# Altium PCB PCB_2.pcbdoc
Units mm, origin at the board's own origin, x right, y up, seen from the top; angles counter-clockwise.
Board outline 42.7 x 42.6 mm, 6 copper layers (Top Layer, Inner1, Inner2, Inner3, Inner4, Bottom Layer); 29 components, 49 nets, 154 pads, 103 vias.
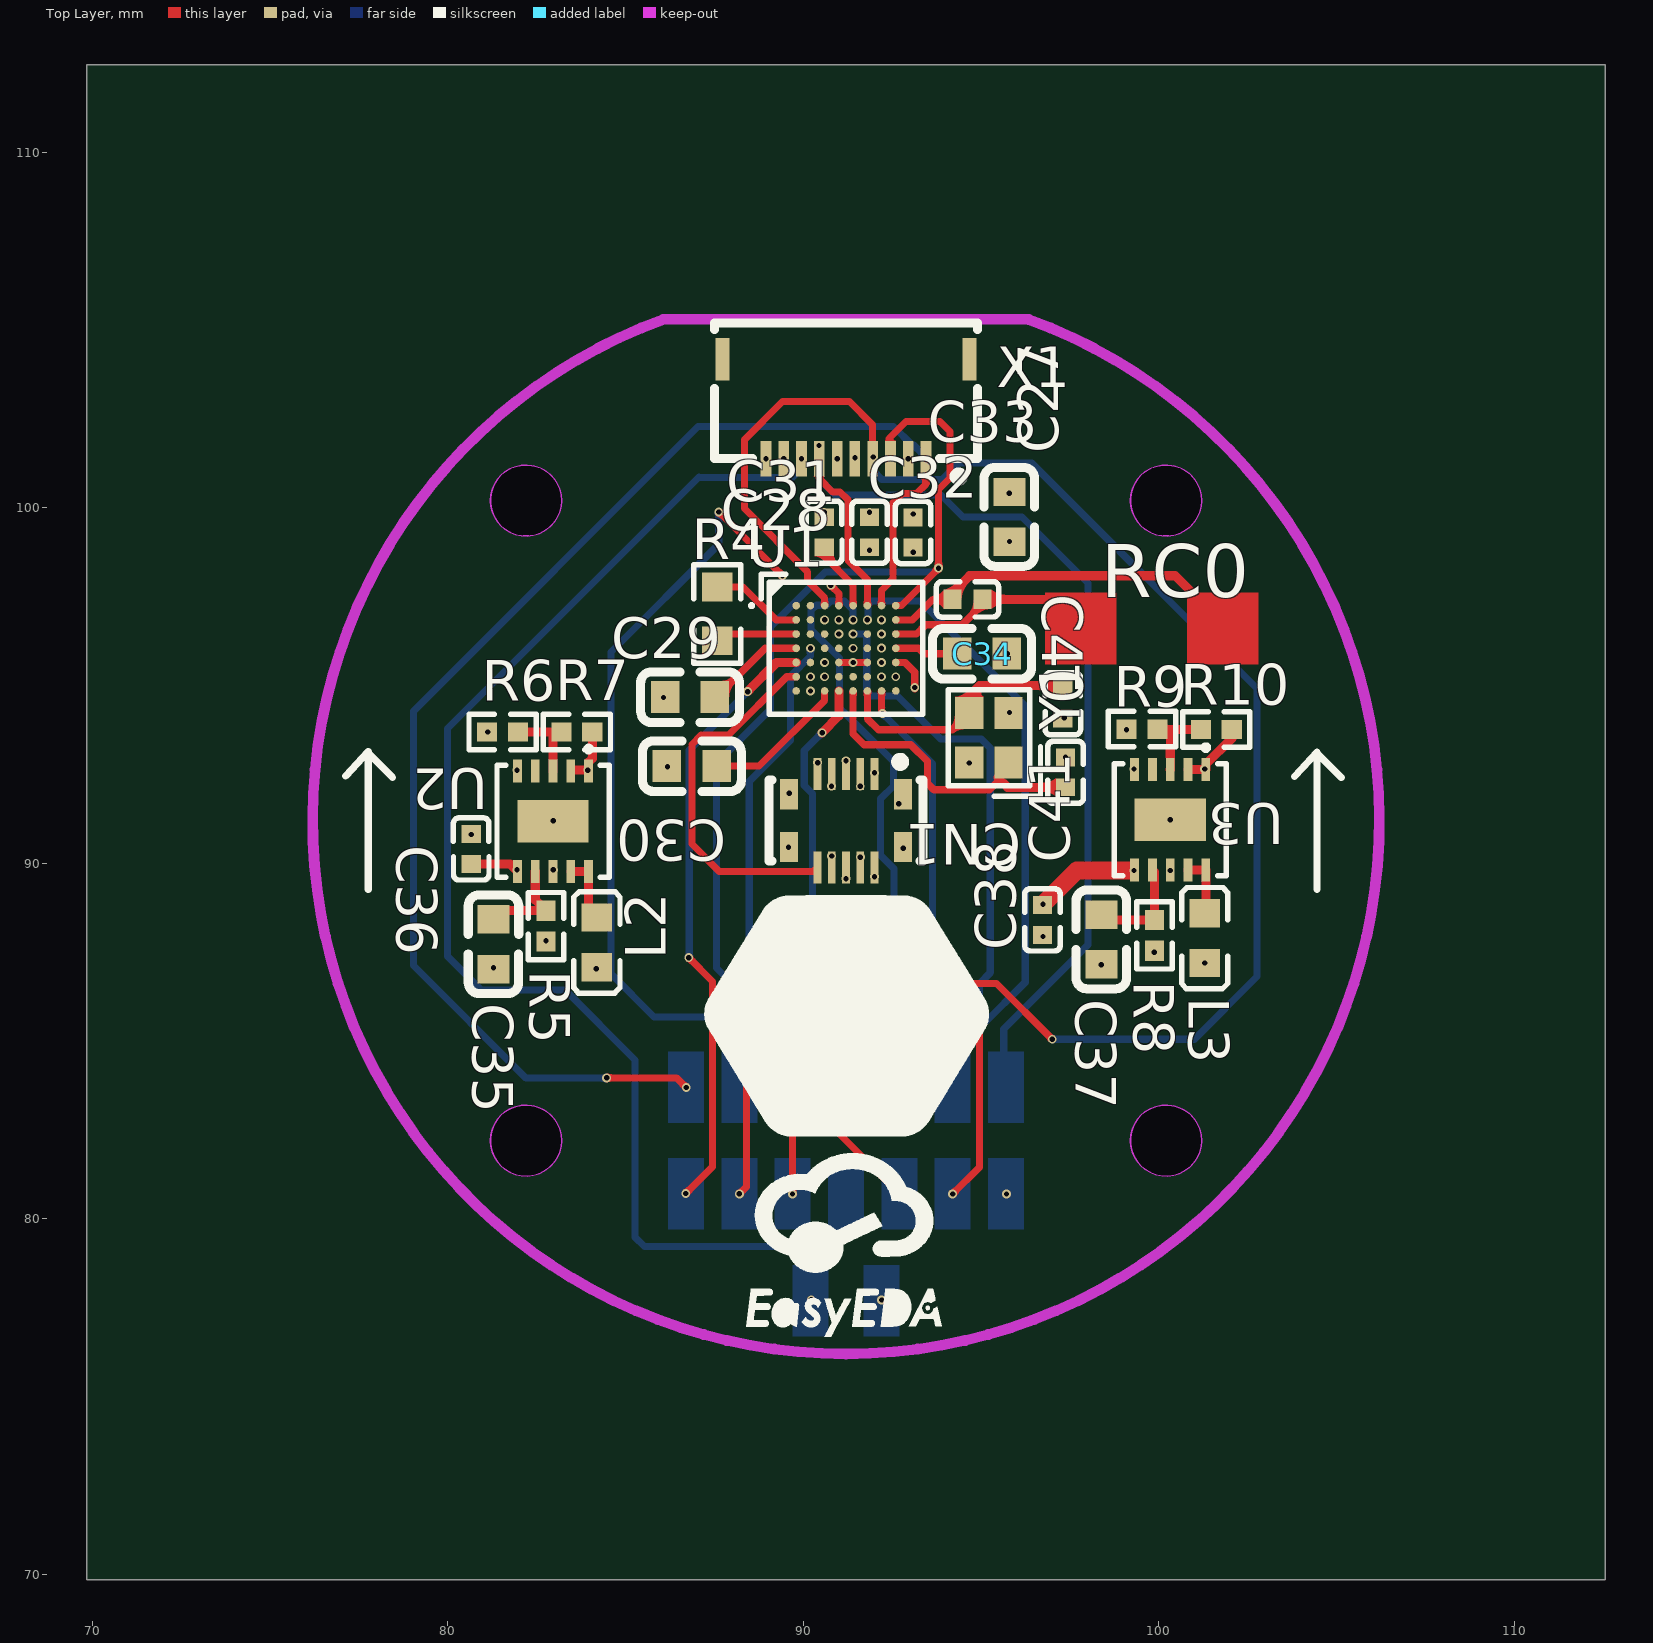
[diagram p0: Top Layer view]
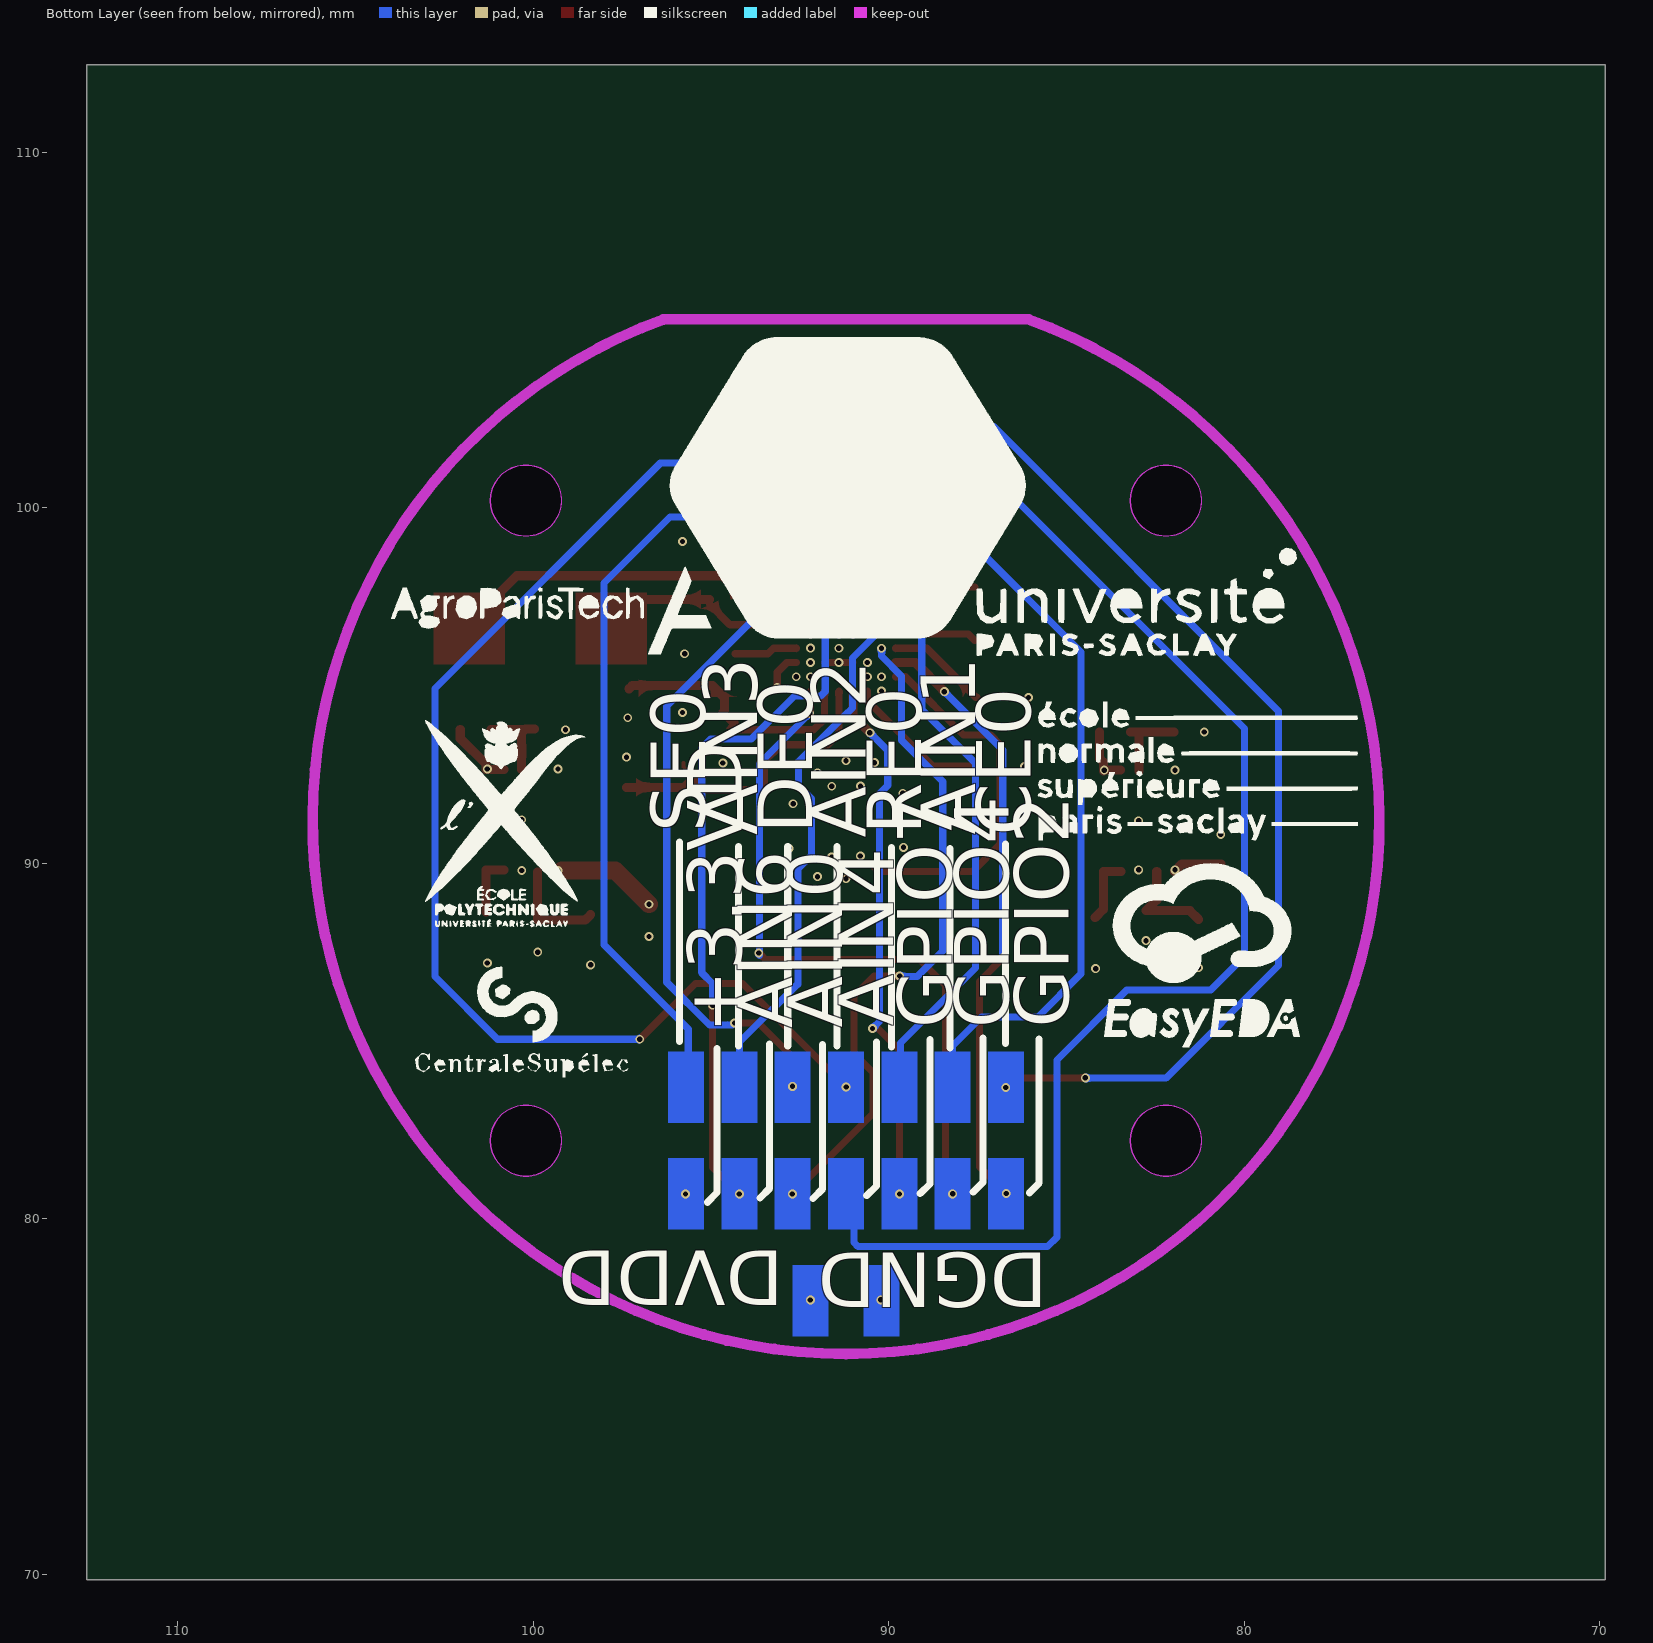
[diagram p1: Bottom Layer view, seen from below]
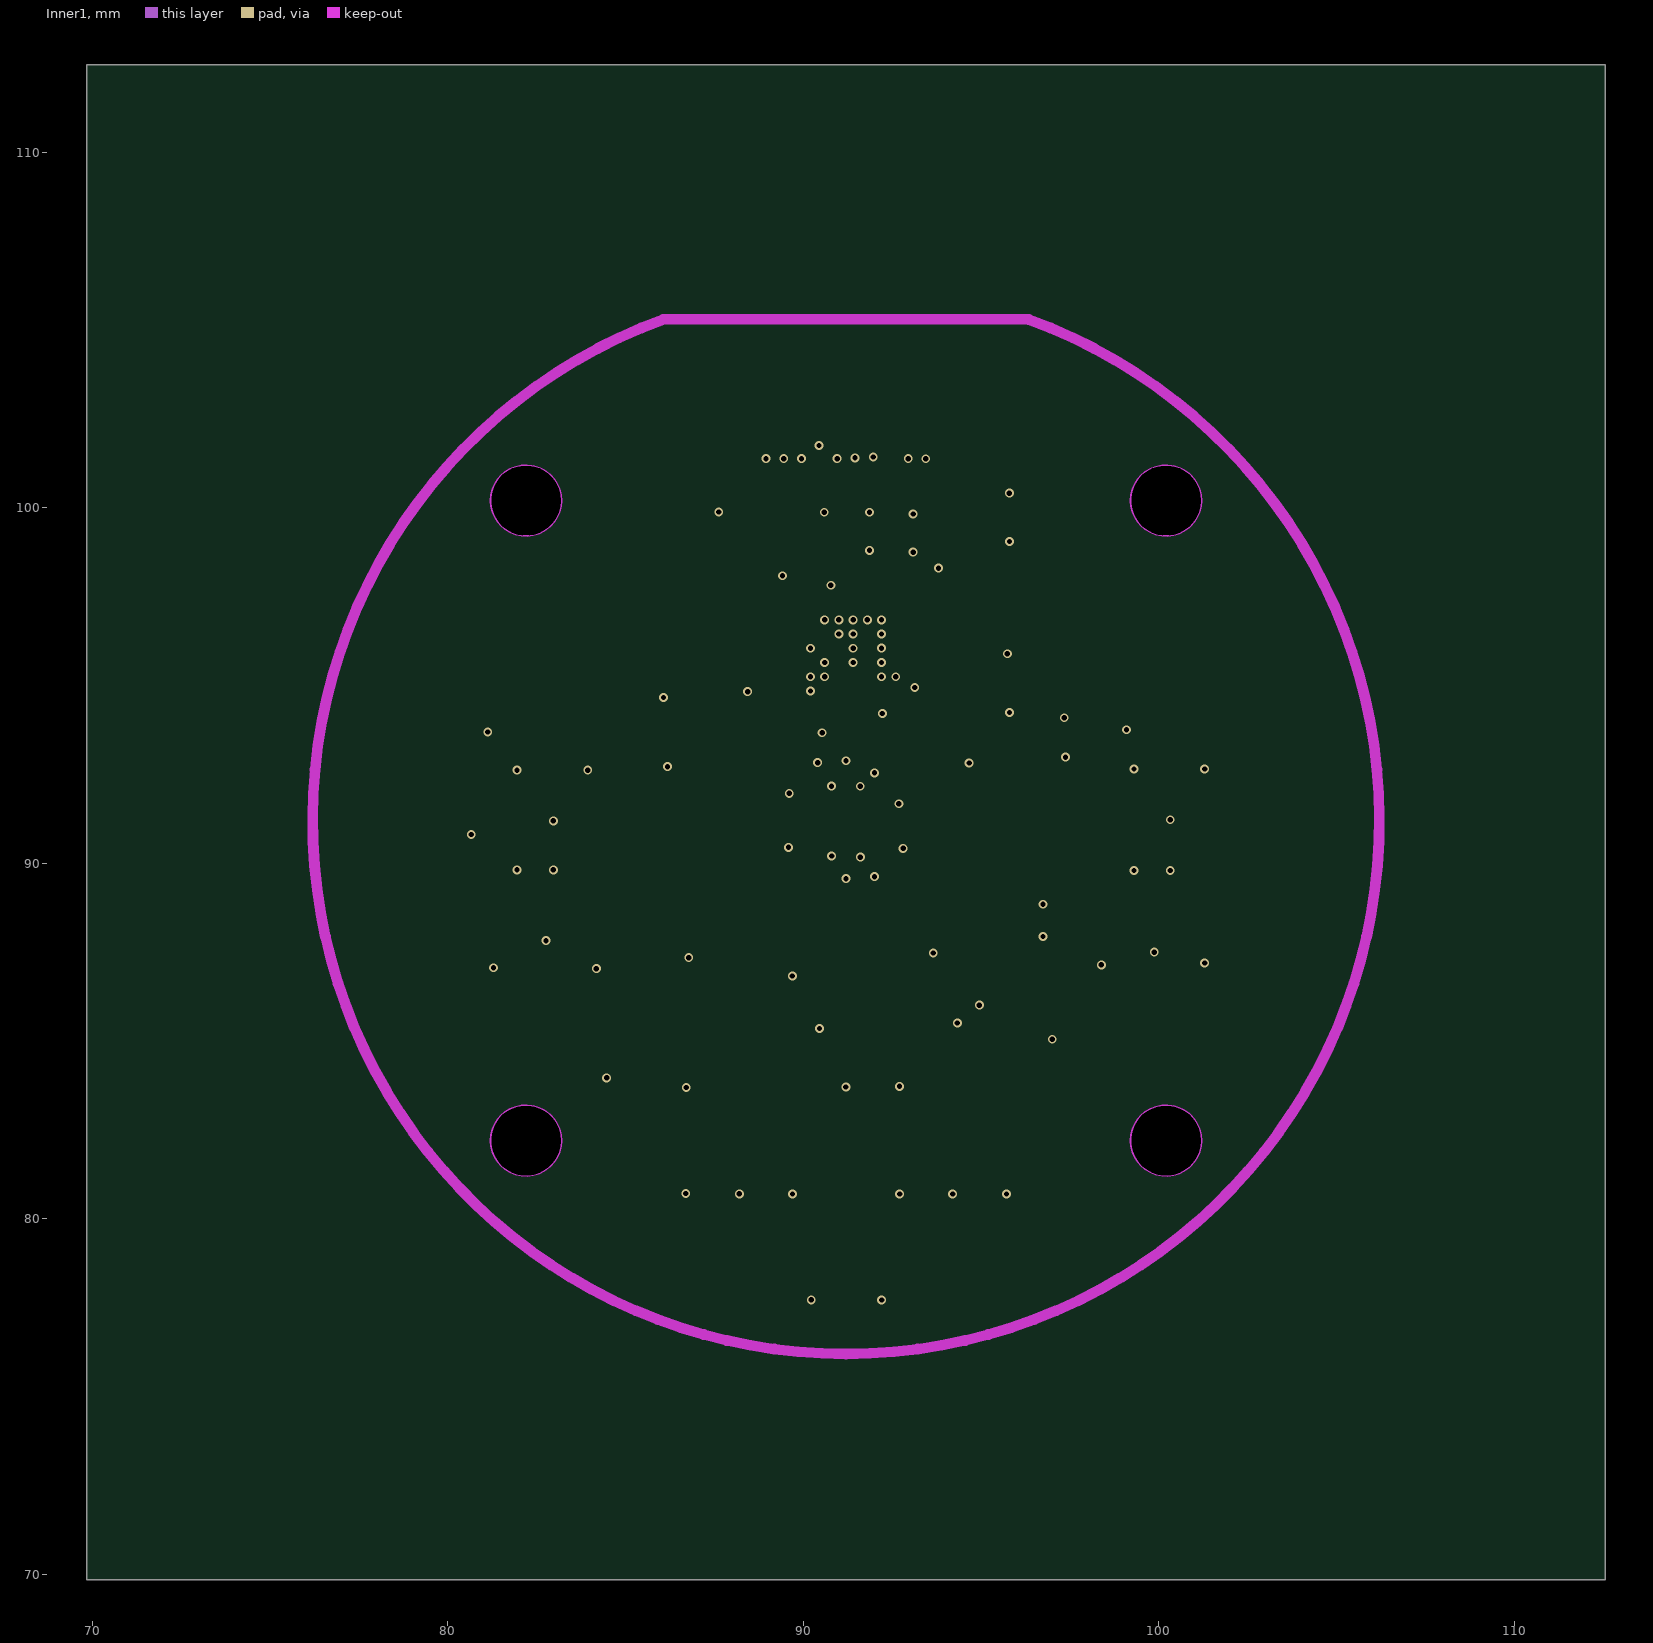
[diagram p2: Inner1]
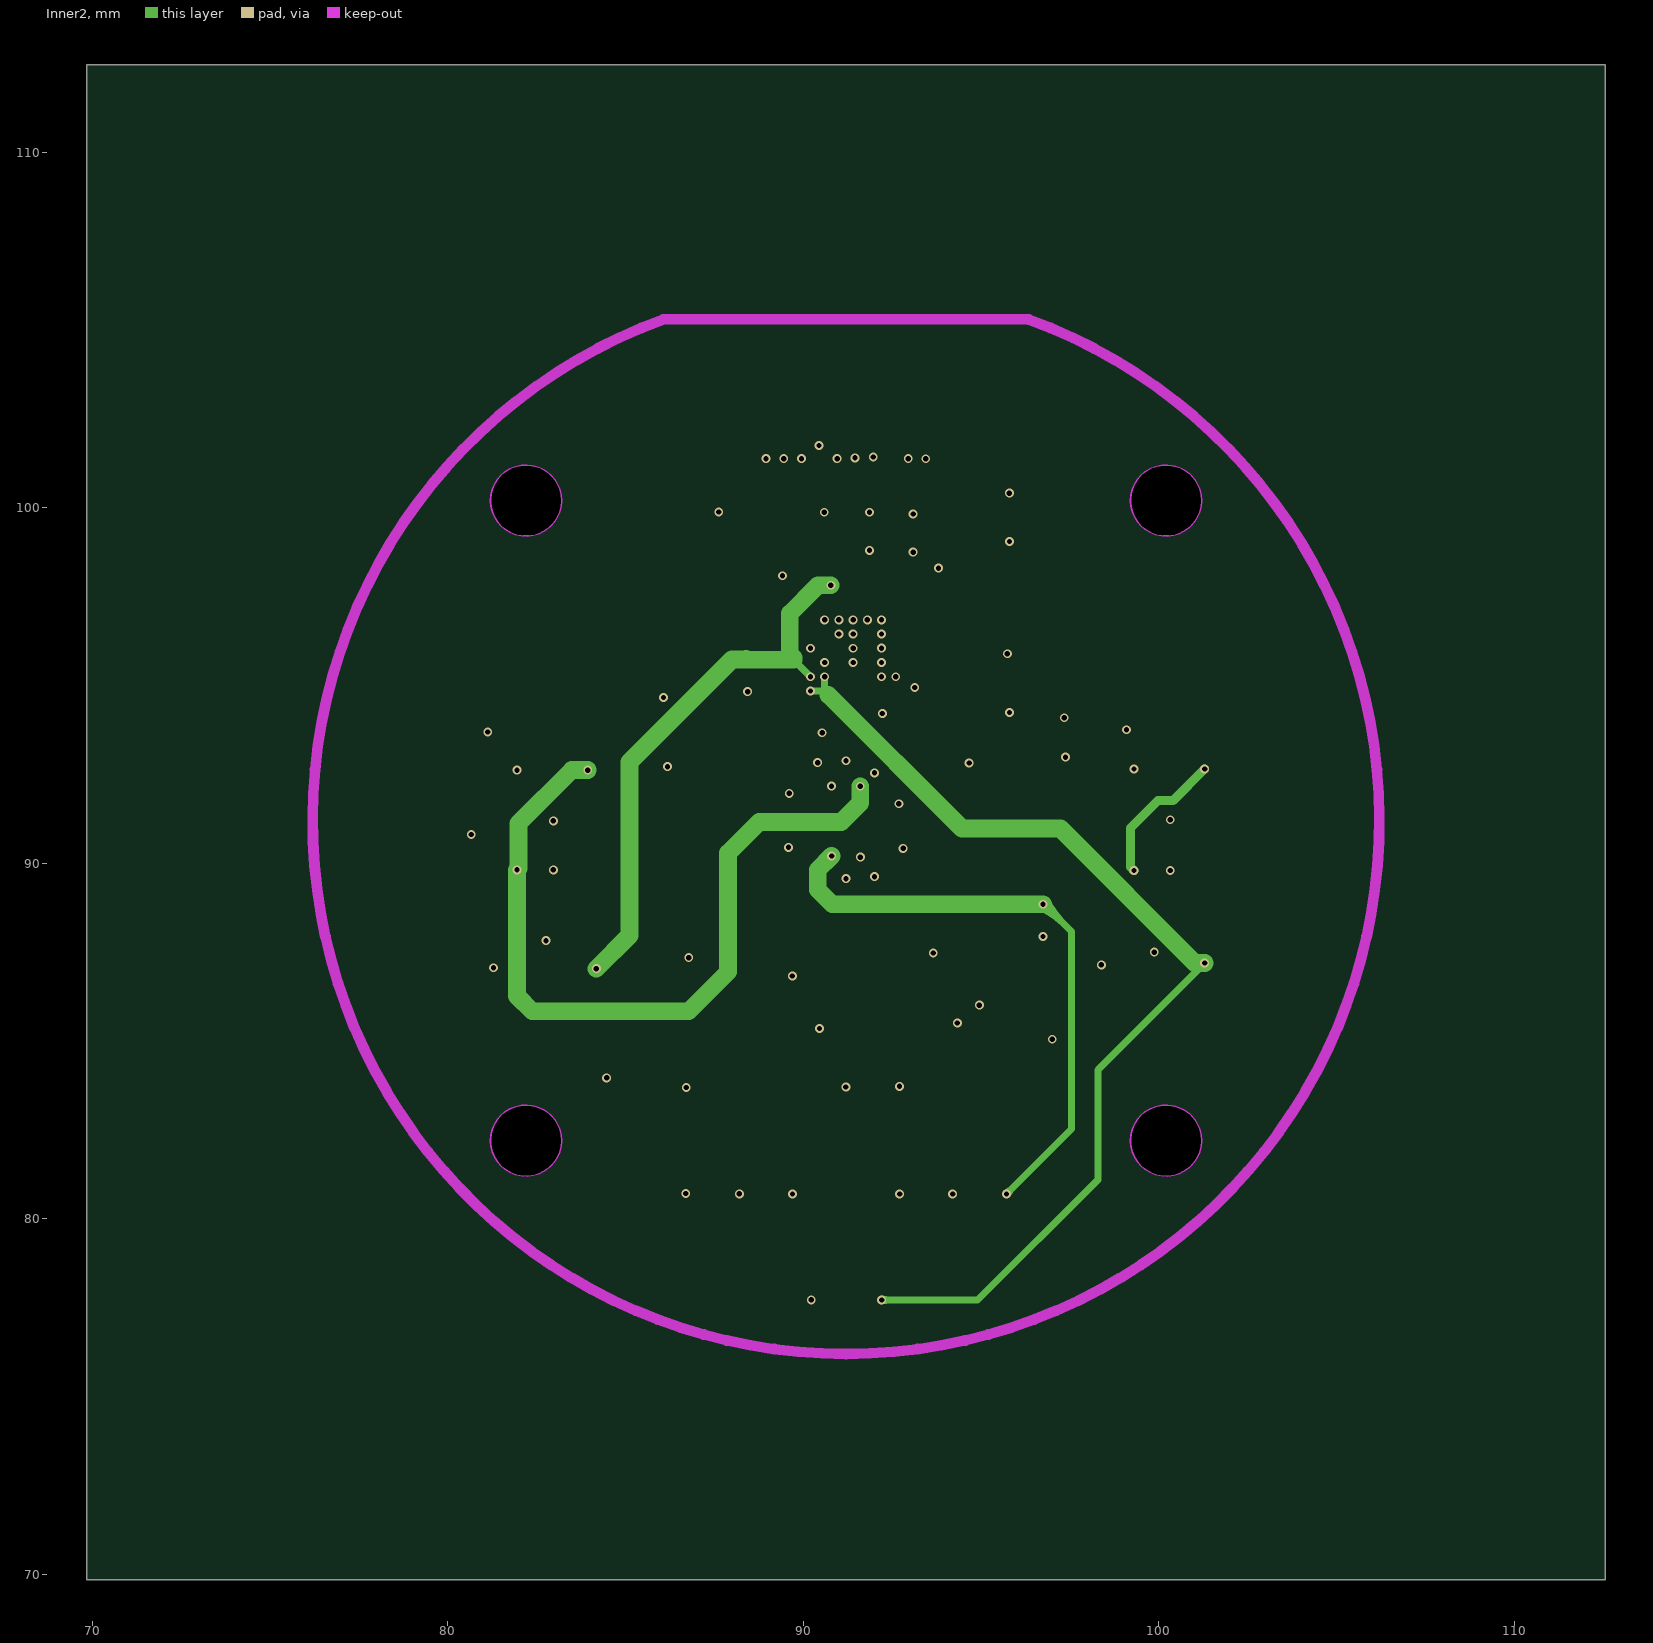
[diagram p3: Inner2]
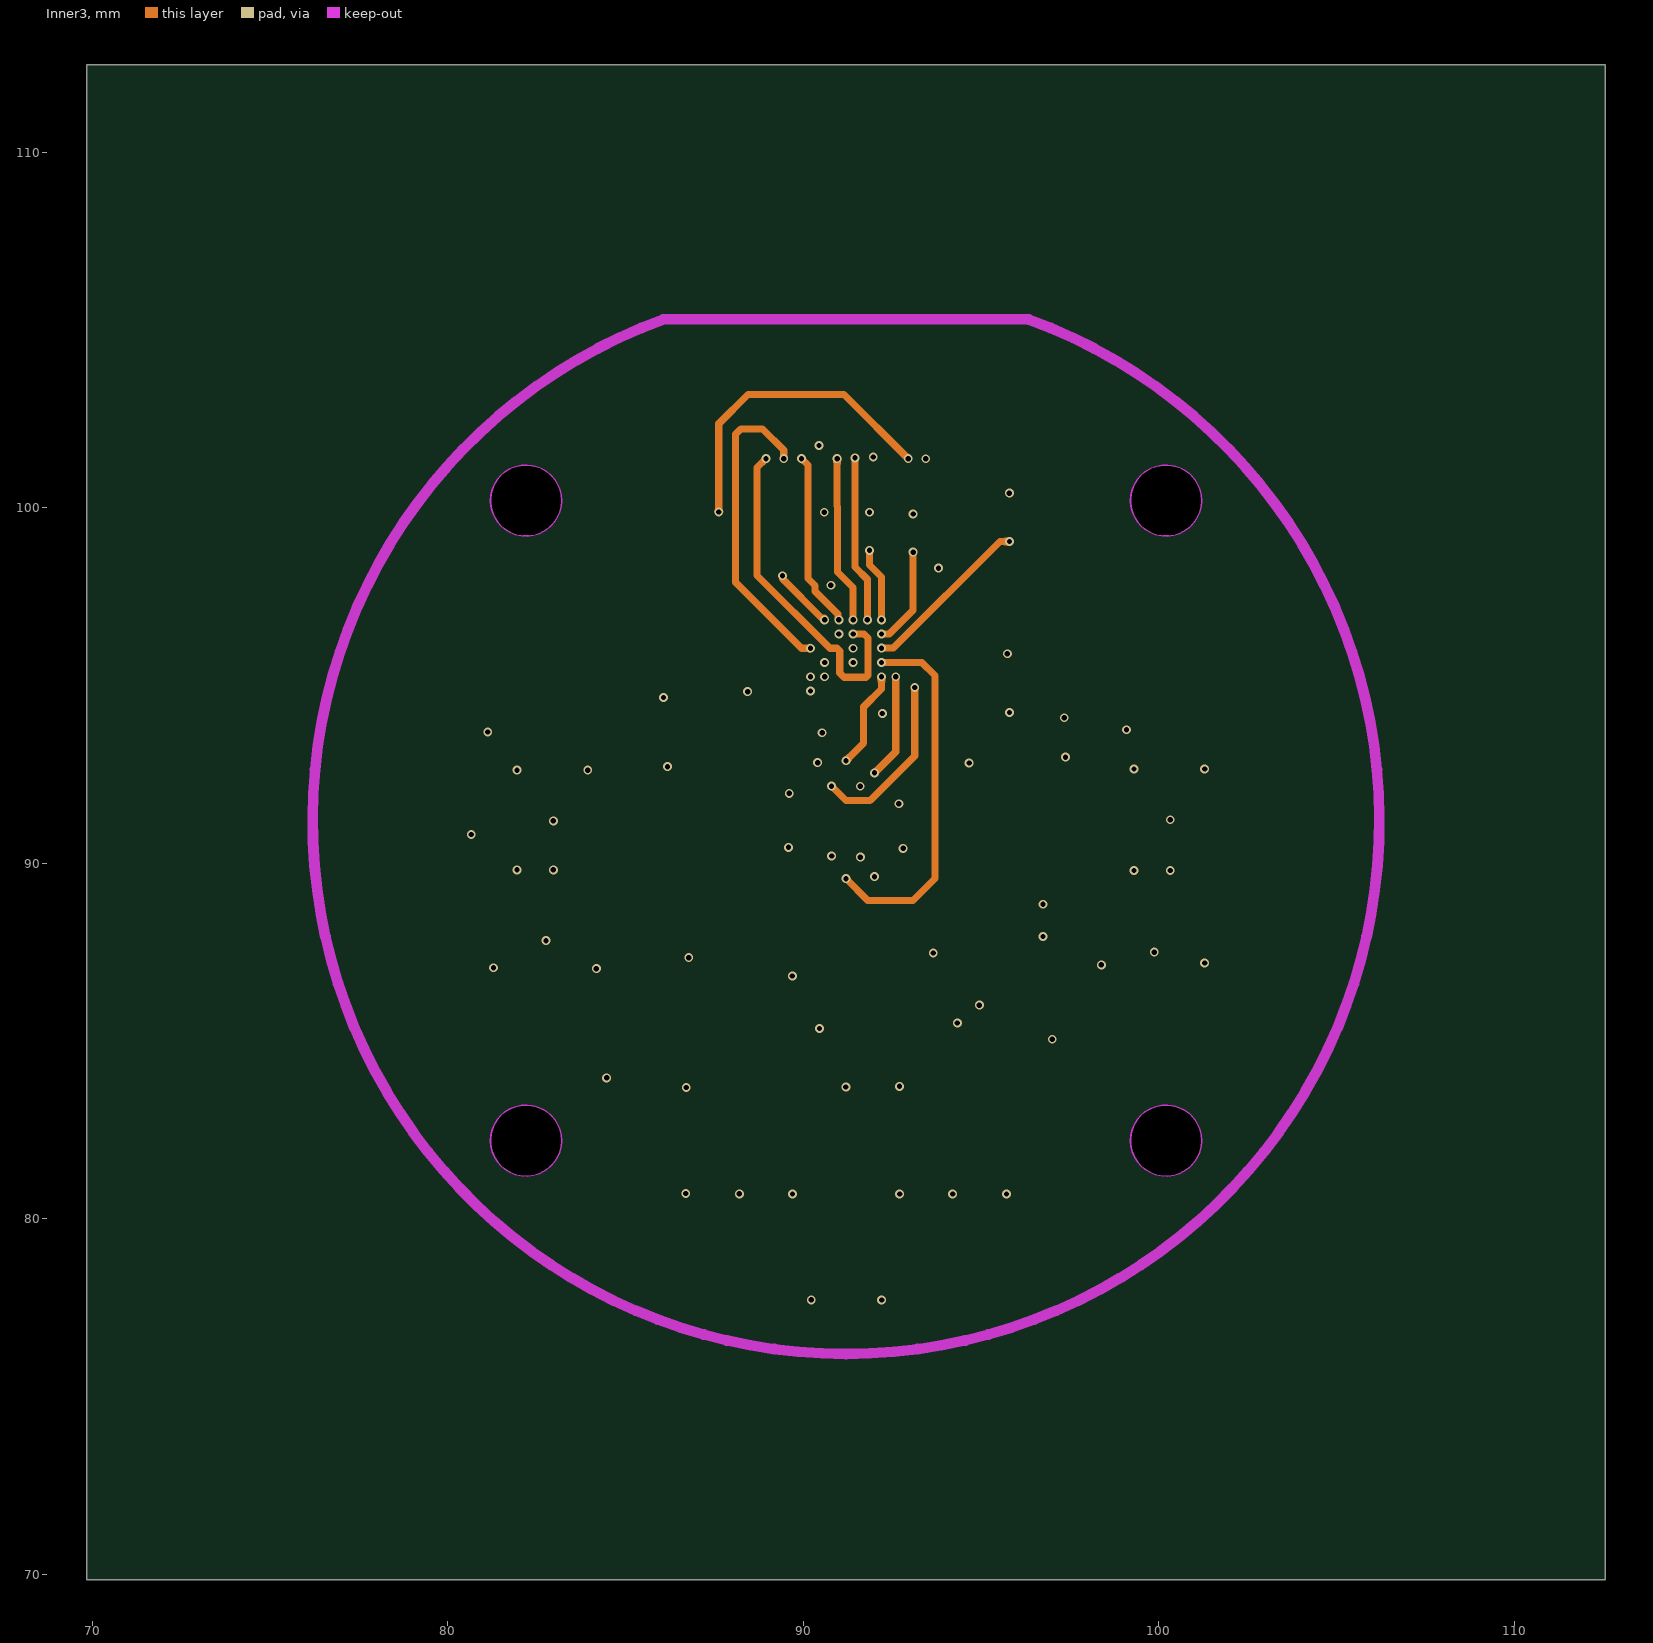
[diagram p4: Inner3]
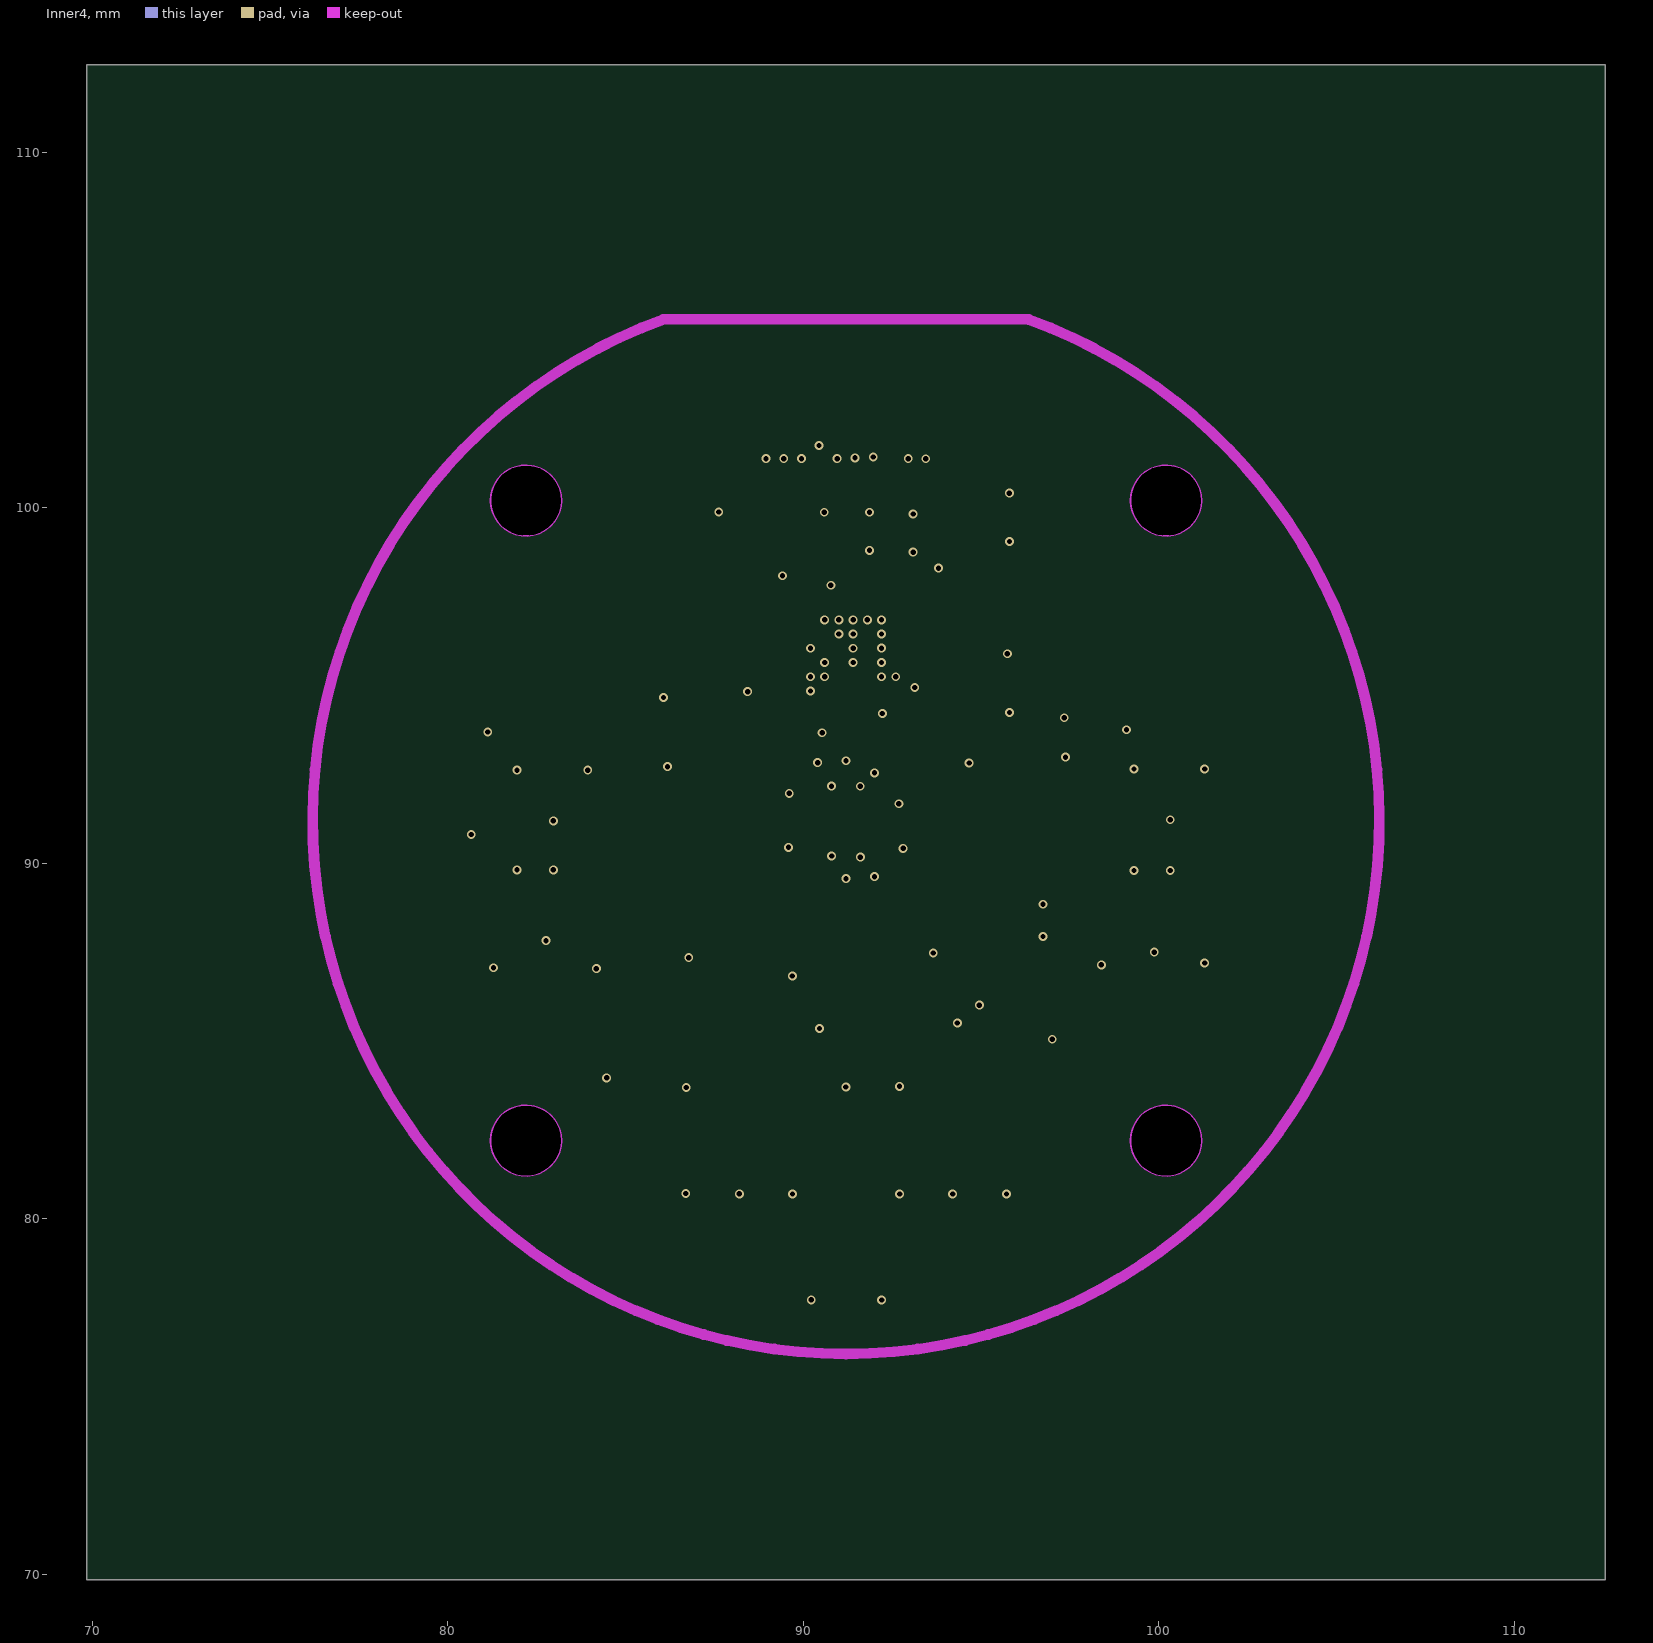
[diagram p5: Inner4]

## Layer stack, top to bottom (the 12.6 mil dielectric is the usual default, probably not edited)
Top Layer: signal copper (thickness not stored)
Dielectric: dielectric 0.32, FR-4, Dk 4.8
Inner1: signal copper (thickness not stored)
Dielectric: dielectric 0.32, FR-4, Dk 4.8
Inner2: signal copper (thickness not stored)
Dielectric: dielectric 0.32, FR-4, Dk 4.8
Inner3: signal copper (thickness not stored)
Dielectric: dielectric 0.32, FR-4, Dk 4.8
Inner4: signal copper (thickness not stored)
Dielectric: dielectric 0.32, FR-4, Dk 4.8
Bottom Layer: signal copper (thickness not stored)

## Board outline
112.55,69.85 69.85,69.85 69.85,112.453 112.55,112.453
cut-out: 101.2,100.2 cw(c100.2,100.2) 99.2,100.2 cw(c100.2,100.2)
cut-out: 101.2,82.2 cw(c100.2,82.2) 99.2,82.2 cw(c100.2,82.2)
cut-out: 83.2,82.2 cw(c82.2,82.2) 81.2,82.2 cw(c82.2,82.2)
cut-out: 83.2,100.2 cw(c82.2,100.2) 81.2,100.2 cw(c82.2,100.2)

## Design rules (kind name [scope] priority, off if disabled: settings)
BoardOutlineClearance copperThickness1oz [All] p0: genericclearance=0.254 ignorepadtopadclearanceinfootprint=FALSE except(0: Arc-SplitContinuation Track-SplitContinuation SMDPad-SplitContinuation THPad-SplitContinuation Via-SplitContinuation Fill-SplitContinuation Poly-SplitContinuation Region-SplitContinuation Text-SplitContinuation; 0.152: SMDPad-CutoutEdge THPad-CutoutEdge Via-CutoutEdge Fill-CutoutEdge Region-CutoutEdge; 0.3: Track-OutlineEdge SMDPad-OutlineEdge THPad-OutlineEdge Via-OutlineEdge Fill-OutlineEdge Region-OutlineEdge Poly-OutlineEdge Text-OutlineEdge Track-CutoutEdge)
BoardOutlineClearance copperThickness2oz [All] p0: genericclearance=0.254 ignorepadtopadclearanceinfootprint=FALSE except(0: Arc-SplitContinuation Track-SplitContinuation SMDPad-SplitContinuation THPad-SplitContinuation Via-SplitContinuation Fill-SplitContinuation Poly-SplitContinuation Region-SplitContinuation Text-SplitContinuation; 0.152: SMDPad-CutoutEdge THPad-CutoutEdge Via-CutoutEdge Fill-CutoutEdge Region-CutoutEdge; 0.3: Track-OutlineEdge SMDPad-OutlineEdge THPad-OutlineEdge Via-OutlineEdge Fill-OutlineEdge Region-OutlineEdge Poly-OutlineEdge Text-OutlineEdge Track-CutoutEdge)
BoardOutlineClearance copperThicknessInner0.5oz [All] p0: genericclearance=0.254 ignorepadtopadclearanceinfootprint=FALSE except(0: Arc-SplitContinuation Track-SplitContinuation SMDPad-SplitContinuation THPad-SplitContinuation Via-SplitContinuation Fill-SplitContinuation Poly-SplitContinuation Region-SplitContinuation Text-SplitContinuation; 0.152: SMDPad-CutoutEdge THPad-CutoutEdge Via-CutoutEdge Fill-CutoutEdge Region-CutoutEdge; 0.3: Track-OutlineEdge SMDPad-OutlineEdge THPad-OutlineEdge Via-OutlineEdge Fill-OutlineEdge Region-OutlineEdge Poly-OutlineEdge Text-OutlineEdge Track-CutoutEdge)
Clearance copperThickness1oz [(InNet('X1') OR InNet('DGND') OR InNet('X0') OR InNet('DVDD') OR InNet('AGND') OR InNet('AVDD') OR InNet('$1N2048') OR InNet('$1N2152') OR InNet('$1N2188') OR InNet('$1N2486') OR InNet('$1N2550') OR InNet('$1N3554') OR InNet('RC0_1') OR InNet('RC0_0') OR InNet('$1N4271') OR InNet('$1N3580') OR InNet('$1N3572') OR InNet('CE0') OR InNet('AIN1') OR InNet('RE0') OR InNet('AIN2') OR InNet('DE0') OR InNet('AIN3') OR InNet('SE0') OR InNet('AIN4') OR InNet('AIN0') OR InNet('AIN6') OR InNet('GPIO2') OR InNet('RESET') OR InNet('GPIO3') OR InNet('GPIO6') OR InNet('GPIO7') OR InNet('GPIO0') OR InNet('RC0_2') OR InNet('GPIO1') OR InNet('GPIO5') OR InNet('MOSI') OR InNet('CS') OR InNet('GPIO4') OR InNet('MISO') OR InNet('SCLK') OR InNet('$1N7940') OR InNet('$1N7995') OR InNet('+3.3VA') OR InNet('$1N8877') OR InNet('+3.3VD') OR InNet('$1N8870') OR InNet('$1N8461') OR InNet('$1N8893'))] p1: gap=0.178 ignorepadtopadclearanceinfootprint=FALSE except(0.102: Track-Track; 0.14: Via-Via; 0.152: Track-SMDPad SMDPad-SMDPad Track-THPad SMDPad-THPad THPad-THPad Track-Via SMDPad-Via THPad-Via Track-Fill SMDPad-Fill THPad-Fill Via-Fill Fill-Fill SMDPad-Region THPad-Region Via-Region Fill-Region Region-Region Track-Poly SMDPad-Poly THPad-Poly Via-Poly Fill-Poly Poly-Poly Track-Text SMDPad-Text THPad-Text Via-Text Fill-Text Region-Text Poly-Text Text-Text; 0.175: Track-Hole SMDPad-Hole THPad-Hole Via-Hole Fill-Hole Region-Hole Poly-Hole Text-Hole Sheet-Hole; 0.3: Track-Region Region-Poly Track-Sheet SMDPad-Sheet THPad-Sheet Via-Sheet Fill-Sheet Region-Sheet Poly-Sheet Text-Sheet)
Clearance copperThickness2oz [All] p1: gap=0.178 ignorepadtopadclearanceinfootprint=FALSE except(0.152: Track-SMDPad SMDPad-SMDPad Track-THPad SMDPad-THPad THPad-THPad Track-Via SMDPad-Via THPad-Via Via-Via Track-Fill SMDPad-Fill THPad-Fill Via-Fill Fill-Fill SMDPad-Region THPad-Region Via-Region Fill-Region Region-Region Track-Poly SMDPad-Poly THPad-Poly Via-Poly Fill-Poly Poly-Poly Track-Text SMDPad-Text THPad-Text Via-Text Fill-Text Region-Text Poly-Text Text-Text; 0.175: Track-Hole SMDPad-Hole THPad-Hole Via-Hole Fill-Hole Region-Hole Poly-Hole Text-Hole Sheet-Hole; 0.203: Track-Track; 0.3: Track-Region Region-Poly Track-Sheet SMDPad-Sheet THPad-Sheet Via-Sheet Fill-Sheet Region-Sheet Poly-Sheet Text-Sheet)
Clearance copperThicknessInner0.5oz [All] p1: gap=0.178 ignorepadtopadclearanceinfootprint=FALSE except(0.089: Track-Track; 0.152: Track-SMDPad SMDPad-SMDPad Track-THPad SMDPad-THPad THPad-THPad Track-Via SMDPad-Via THPad-Via Via-Via Track-Fill SMDPad-Fill THPad-Fill Via-Fill Fill-Fill SMDPad-Region THPad-Region Via-Region Fill-Region Region-Region Track-Poly SMDPad-Poly THPad-Poly Via-Poly Fill-Poly Poly-Poly Track-Text SMDPad-Text THPad-Text Via-Text Fill-Text Region-Text Poly-Text Text-Text; 0.175: Track-Hole SMDPad-Hole THPad-Hole Via-Hole Fill-Hole Region-Hole Poly-Hole Text-Hole Sheet-Hole; 0.3: Track-Region Region-Poly Track-Sheet SMDPad-Sheet THPad-Sheet Via-Sheet Fill-Sheet Region-Sheet Poly-Sheet Text-Sheet)
DiffPairsRouting differentialPair [All] p1: maxuncoupledlength=10 minlimit=5.9843 maxlimit=5.9843 mostfreqgap=5.9843 toplayer_minwidth=5 toplayer_prefwidth=10 toplayer_maxwidth=100 bottomlayer_minwidth=5 bottomlayer_prefwidth=10 bottomlayer_maxwidth=100 midlayer1_minwidth=5 midlayer1_prefwidth=10 midlayer1_maxwidth=100 midlayer2_minwidth=5 midlayer2_prefwidth=10 midlayer2_maxwidth=100 midlayer3_minwidth=5 midlayer3_prefwidth=10 midlayer3_maxwidth=100 midlayer4_minwidth=5 midlayer4_prefwidth=10 midlayer4_maxwidth=100
PasteMaskExpansion pasteMaskExpansion [All] p1: expansion=0
PlaneConnect innerPlane [All] p1: planeconnectstyle=Relief reliefexpansion=0.508 reliefentries=4 reliefconductorwidth=0.254 reliefairgap=0.254
PolygonConnect copperRegion [All] p1: connectstyle=Relief reliefentries=4 reliefconductorwidth=10 polygonreliefangle="90 Angle" airgapwidth=10
RoutingVias viaSize [All] p1: viastyle="Through Hole" holewidth=5.9056 minholewidth=3.937 maxholewidth=248.0314 width=9.8426 minwidth=7.874 maxwidth=393.7008
SolderMaskExpansion solderMaskExpansion [All] p1: useseparateexpansions=TRUE expansion=2.0079 expansionbottom=2.0079
Width copperThickness1oz [All] p1: maxlimit=100 minlimit=4 preferedwidth=10
Width copperThickness2oz [All] p1: maxlimit=100 minlimit=8 preferedwidth=10
Width copperThickness0.5oz [All] p1: maxlimit=100 minlimit=4 preferedwidth=10

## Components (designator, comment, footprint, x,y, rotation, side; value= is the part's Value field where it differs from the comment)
C27 "CL10B474KA8NNNC" C0603 95.793,99.74 r90 top
C28 "CL05A475MP5NRNC" C0402 90.588,99.309 r270 top
C29 "CL10B474KA8NNNC" C0603 86.814,94.668 r0 top
C30 "CL10B474KA8NNNC" C0603 86.865,92.73 r180 top
C31 "CL05B104KO5NNNC" C0402 91.863,99.309 r270 top
C32 "CL05B104KO5NNNC" C0402 93.087,99.302 r270 top
C33 "CL05B104KO5NNNC" C0402 94.617,97.422 r180 top
C34 "CL10B474KA8NNNC" C0603 95.025,95.892 r0 top
C35 "CL10B474KA8NNNC" C0603 81.286,87.722 r270 top
C36 "CL05A475MP5NRNC" C0402 80.66,90.401 r270 top
C37 "CL10B474KA8NNNC" C0603 98.38,87.857 r270 top
C38 "CL05A475MP5NRNC" C0402 96.725,88.405 r90 top
C40 "0402CG150J500NT" C0402 97.298,94.488 r270 top
C41 "0402CG150J500NT" C0402 97.375,92.555 r90 top
CN1 "559099872" CONN-SMD_559099872 91.2,91.2 r180 top locked
L2 "BLM18PG600SN1D" L0603 84.193,87.773 r270 top
L3 "BLM18PG600SN1D" L0603 101.287,87.894 r270 top
R4 "PTFR0603Q100RN9" R0603 87.579,97.014 r270 top
R5 "0402WGF3302TCE" R0402 82.765,88.232 r270 top
R6 "0402WGF3302TCE" R0402 81.541,93.689 r0 top
R7 "0402WGF4702TCE" R0402 83.632,93.689 r0 top
R8 "0402WGF3302TCE" R0402 99.875,87.97 r270 top
R9 "0402WGF3302TCE" R0402 99.525,93.77 r0 top
R10 "0402WGF4702TCE" R0402 101.615,93.76 r0 top
U1 "AD5940BCBZ-RL7" BGA-56_L4.2-W3.6-R8-C7-P0.40-TL 91.2,96.045 r0 top locked
U2 "LT3045EDD#TRPBF_C514420" DFN-10_L3.0-W3.0-P0.50-BL-EP 82.961,91.183 r180 top
U3 "LT3045EDD#TRPBF_C514420" DFN-10_L3.0-W3.0-P0.50-BL-EP 100.318,91.223 r180 top
X1 "AFC48-S10FKA-HF" FPC-SMD_AFC48-S10FKA-HF 91.2,102.777 r180 top
Y1 "XL7EL89CKI-111YLC-32M" CRYSTAL-SMD_4P-L2.0-W1.6-BL 95.22,93.53 r90 top

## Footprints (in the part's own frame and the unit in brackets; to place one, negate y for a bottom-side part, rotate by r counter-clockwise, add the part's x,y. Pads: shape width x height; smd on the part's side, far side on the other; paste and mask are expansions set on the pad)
BGA-56_L4.2-W3.6-R8-C7-P0.40-TL [mil]
  round 8.41 smd: A1(-55.12,47.24) A2(-39.37,47.24) A3(-23.62,47.24) A4(-7.87,47.24) A5(7.87,47.24) A6(23.62,47.24) A7(39.37,47.24) A8(55.12,47.24) B1(-55.12,31.5) B2(-39.37,31.5) B3(-23.62,31.5) B4(-7.87,31.5) B5(7.87,31.5) B6(23.62,31.5) B7(39.37,31.5) B8(55.12,31.5) C1(-55.12,15.75) C2(-39.37,15.75) C3(-23.62,15.75) C4(-7.87,15.75) C5(7.87,15.75) C6(23.62,15.75) C7(39.37,15.75) C8(55.12,15.75) D1(-55.12,0) D2(-39.37,0) D3(-23.62,0) D4(-7.87,0) D5(7.87,0) D6(23.62,0) D7(39.37,0) D8(55.12,0) E1(-55.12,-15.75) E2(-39.37,-15.75) E3(-23.62,-15.75) E4(-7.87,-15.75) E5(7.87,-15.75) E6(23.62,-15.75) E7(39.37,-15.75) E8(55.12,-15.75) F1(-55.12,-31.5) F2(-39.37,-31.5) F3(-23.62,-31.5) F4(-7.87,-31.5) F5(7.87,-31.5) F6(23.62,-31.5) F7(39.37,-31.5) F8(55.12,-31.5) G1(-55.12,-47.24) G2(-39.37,-47.24) G3(-23.62,-47.24) G4(-7.87,-47.24) G5(7.87,-47.24) G6(23.62,-47.24) G7(39.37,-47.24) G8(55.12,-47.24)
  silkscreen extent -107,-73 85,82
C0402 [mm]
  rect 0.5x0.54 smd: 1(-0.42,0) 2(0.42,0)
  silkscreen extent -0.87,-0.5 0.87,0.5
C0603 [mm]
  rect 0.8x0.9 smd: 1(-0.7,0) 2(0.7,0)
  silkscreen extent -1.39,-0.71 1.39,0.71
CONN-SMD_559099872 [mm]
  rect 0.22x0.9 smd: 1(-0.8,-1.315) 2(-0.4,-1.315) 3(0,-1.315) 4(0.4,-1.315) 5(0.8,-1.315) 6(0.8,1.315) 7(0.4,1.315) 8(0,1.315) 9(-0.4,1.315) 10(-0.8,1.315)
  rect 0.5x0.85 smd: 11(-1.6,0.74) 12(-1.6,-0.74) 13(1.6,-0.74) 14(1.6,0.74)
  silkscreen extent -2.16,-1.78 2.16,1.14
CRYSTAL-SMD_4P-L2.0-W1.6-BL [mm]
  rect 0.9x0.8 smd: 1(-0.7,-0.55) 2(0.7,-0.55) 3(0.7,0.55) 4(-0.7,0.55)
  silkscreen extent -1.65,-1.45 1.35,1.15
DFN-10_L3.0-W3.0-P0.50-BL-EP [mm]
  rect 0.25x0.65 smd: 1(-1,-1.411) 2(-0.5,-1.411) 3(0,-1.411) 4(0.5,-1.411) 5(1,-1.411) 6(1,1.411) 7(0.5,1.411) 8(0,1.411) 9(-0.5,1.411) 10(-1,1.411)
  rect 2x1.2 smd: 11(0,0)
  silkscreen extent -1.58,-2.1 1.58,1.58
FPC-SMD_AFC48-S10FKA-HF [mm]
  rect 0.3x1 smd: 1(-2.25,1.4) 2(-1.75,1.4) 3(-1.25,1.4) 4(-0.75,1.4) 5(-0.25,1.4) 6(0.25,1.4) 7(0.75,1.4) 8(1.25,1.4) 9(1.75,1.4) 10(2.25,1.4)
  rect 0.4x1.2 smd: 11(-3.475,-1.4) 12(3.475,-1.4)
  silkscreen extent -3.7,-2.42 3.7,2.03
L0603 [mm]
  rect 0.8x0.864 smd: 1(-0.7,0) 2(0.7,0)
  silkscreen extent -1.42,-0.65 1.42,0.65
R0402 [mm]
  rect 0.566x0.54 smd: 1(-0.433,0) 2(0.433,0)
  silkscreen extent -0.94,-0.5 0.94,0.5
R0603 [mm]
  rect 0.806x0.864 smd: 1(-0.753,0) 2(0.753,0)
  silkscreen extent -1.39,-0.66 1.39,0.66

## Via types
v1: diameter 0.25, hole 0.15, Top Layer to Bottom Layer, 103 vias

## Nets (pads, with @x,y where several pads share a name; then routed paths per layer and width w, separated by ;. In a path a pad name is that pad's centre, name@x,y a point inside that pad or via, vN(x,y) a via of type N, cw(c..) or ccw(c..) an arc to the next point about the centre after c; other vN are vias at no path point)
$1N2048: C27.1 U1.D7 | length 4.8
  Inner3 w0.2: v1(92.2,96.049) 92.53,96.049 95.529,99.048 v1(95.8,99.048)
$1N2152: C28.2 U1.A5 | length 1.9
  Top Layer w0.2: C28.2@90.588,98.764 90.588,98.64 91.4,97.828 U1.A5
$1N2188: C29.2 U1.D1 | length 2.9
  Top Layer w0.2: C29.2 87.55,94.668 88.927,96.045 U1.D1
$1N2486: C30.1 U1.G3 | length 4.1
  Top Layer w0.2: C30.1 88.752,92.73 90.6,94.578 U1.G3
$1N2550: C31.2 U1.B7 | length 2.1
  Inner3 w0.2: v1(91.863,98.799) 91.863,98.39 92.2,98.053 v1(92.2,96.845)
$1N3554: C32.2 U1.C7 | length 2.8
  Inner3 w0.2: v1(92.2,96.445) 92.416,96.445 93.087,97.116 v1(93.087,98.748)
$1N3572: R4.1 U1.B1 | length 2.6
  Top Layer w0.2: R4.1 88.305,97.767 89.227,96.845 U1.B1
$1N3580: R4.2 U1.C1 | length 2.3
  Top Layer w0.2: R4.2 87.763,96.445 U1.C1
$1N4271: C34.1 U1.D8 | length 1.8
  Top Layer w0.2: U1.D8 93.24,96.045 93.393,95.892 C34.1
$1N7940: L2.1 U2.9 U2.10 | length 1.9
  Top Layer w0.255: U2.9 U2.10 83.961,88.706 L2.1
$1N7995: C35.1 R5.1 U2.7 | length 2.8
  Top Layer w0.255: C35.1 81.529,88.665 R5.1 82.46,88.97 U2.7
$1N8461: R6.2 R7.1 U2.3 | length 2.3
  Top Layer w0.102: R7.1@82.961,93.63 R7.1@83.02,93.689
  Top Layer w0.255: R6.2 83.02,93.689 R7.1 ; U2.3 R7.1@82.961,93.63
$1N8870: L3.1 U3.9 U3.10 | length 1.7
  Top Layer w0.102: L3.1 L3.1@101.318,88.625
  Top Layer w0.255: U3.9 U3.10 L3.1@101.318,88.625
$1N8877: C37.1 R8.1 U3.7 | length 3
  Top Layer w0.102: U3.7 U3.7@99.875,89.755
  Top Layer w0.255: C37.1 98.535,88.403 R8.1 U3.7@99.875,89.755
$1N8893: R9.2 R10.1 U3.3 | length 2.3
  Top Layer w0.102: 100.267,93.722 100.305,93.76
  Top Layer w0.255: R9.2 R9.2@100.22,93.77 ; 100.267,93.722 100.323,93.667 100.323,92.639 U3.3 ; 100.305,93.76 R10.1
+3.3VA: C36.2 CN1.2 R7.2 U2.1 U2.2 U2.6 | length 25.1
  Top Layer w0.102: U2.2 U2.2@83.484,92.618
  Top Layer w0.255: C36.2 81.751,89.981 U2.6 ; U2.2@83.484,92.618 v1(83.938,92.618) ; U2.1 83.961,92.845 84.065,92.949 R7.2
  Inner2 w0.5: v1(83.938,92.618) 83.489,92.618 81.986,91.115 81.986,89.85 v1(81.949,89.813) 81.949,86.266 82.375,85.84 86.78,85.84 87.885,86.945 87.885,90.285 88.76,91.16 91.065,91.16 91.6,91.695 v1(91.6,92.165)
+3.3VD: C38.2 CN1.7 R10.2 U3.1 U3.2 U3.6 | length 25.6
  Top Layer w0.255: U3.2 U3.1 101.318,92.779 102.048,93.508 R10.2
  Top Layer w0.5: v1(96.74,88.845) 97.69,89.795 v1@99.185,89.795
  Inner2 w0.2: v1(95.715,80.699) 97.54,82.525 97.54,88.082 v1@96.778,88.845
  Inner2 w0.255: v1(99.298,89.795) 99.196,89.897 99.196,90.983 99.973,91.76 100.396,91.76 v1(101.287,92.651)
  Inner2 w0.5: v1(90.795,90.205) 90.405,89.815 90.405,89.255 90.815,88.845 v1(96.74,88.845)
AGND: C27.2 C28.1 C29.1 C31.1 C32.1 C34.2 C35.2 C36.1 R5.2 R6.1 U1.C4 U1.D5 U1.E3 U2.5 U2.8 U2.11
  other v1: 81.286,87.059 82.765,87.824 82.969,89.813 80.66,90.809 82.969,91.19 81.949,92.618 81.125,93.69 86.07,94.66 90.6,95.645 95.739,95.892 91.4,96.045 91,96.445 93.087,99.819 90.588,99.87 91.863,99.87 95.795,100.408
AIN0: U1.D2 X1.9 | length 27.9
  Top Layer w0.2: v1(89.692,86.827) 90.407,86.827 90.972,86.262 90.972,84.642 90.442,84.112 90.442,82.962 v1(92.708,80.697)
  Inner3 w0.2: v1(89.45,101.377) 89.45,101.62 88.854,102.216 88.242,102.216 88.089,102.063 88.089,97.901 89.945,96.045 v1(90.2,96.045)
  Bottom Layer w0.2: v1@89.702,86.82 89.192,86.82 88.48,87.532 88.48,92.3 89.637,93.458 89.637,95.261 90.2,95.823 v1(90.2,96.045)
AIN1: U1.B3 X1.2 | length 32.7
  Top Layer w0.2: v1@87.625,99.875 v1(89.415,98.085)
  Inner3 w0.102: v1(90.6,96.845) v1@90.6,96.9
  Inner3 w0.2: v1(87.622,99.875) 87.622,102.362 88.446,103.185 91.142,103.185 v1(92.95,101.377) ; v1(89.415,98.085) 89.415,98 90.515,96.9 v1@90.6,96.9
  Bottom Layer w0.2: v1(87.622,99.875) 87.622,98.973 84.59,95.94 84.59,86.89 85.802,85.677 87.385,85.677 88.202,84.86 88.202,84.095
AIN2: U1.A3 X1.4 | length 47.2
  Top Layer w0.2: U1.A3 90.6,97.456 90.122,97.934 90.122,98.194 88.344,99.972 88.344,101.91 89.415,102.981 91.302,102.981 91.95,102.333 X1.4 ; v1(91.198,83.705) 94.113,86.62 95.43,86.62 v1(97,85.05)
  Bottom Layer w0.2: v1(91.965,101.425) 91.95,101.41 91.95,101.052 92.206,100.795 93.905,100.795 94.36,101.25 96.425,101.25 102.761,94.915 102.761,86.812 100.998,85.05 v1(97,85.05)
AIN3: U1.B5 X1.6 | length 22
  Inner3 w0.102: v1@91.398,96.848 v1(91.4,96.845)
  Inner3 w0.2: v1(90.95,101.377) 90.95,100.041 90.965,100.026 90.965,98.19 91.398,97.758 v1@91.398,96.848
  Bottom Layer w0.2: 91.22,94.168 91.02,94.368 91.02,95.77 90.22,96.57 90.22,97.11 90.365,97.255 90.648,97.255 90.77,97.377 91.151,97.377 91.4,97.128 v1(91.4,96.845) ; 91.223,94.168 92.531,92.859 92.531,92.176 92.168,91.813 92.168,90.225 92.548,89.845 92.548,86.592 ; 92.559,86.604 94.193,84.97 94.193,83.505
AIN4: U1.B4 X1.8 | length 43.7
  Inner3 w0.2: v1(89.95,101.377) 90.129,101.198 90.129,98.011 90.329,97.811 90.329,97.649 90.977,97.001 90.977,96.883 v1@91,96.86
  Bottom Layer w0.2: 87.057,100.845 89.687,100.845 89.955,101.113 v1@89.955,101.382 ; 87.065,100.855 87.057,100.848 87.055,100.845 79.994,93.785 79.994,87.382 80.942,86.435 83.305,86.435 85.27,84.47 85.27,79.482 85.53,79.222 90.867,79.222 90.979,79.333 90.979,80.608 91.147,80.777 ; v1(89.95,101.377) v1@89.955,101.382 ; 89.955,101.554 v1@89.955,101.382
  other v1: 91,96.845
AIN6: U1.C5 X1.10 | length 28.7
  Top Layer w0.2: v1(94.198,80.697) 94.95,81.45 v1(94.95,86.01)
  Inner3 w0.2: v1(88.95,101.377) 88.701,101.128 88.701,98.094 90.75,96.045 90.945,96.045 91.023,95.967 91.023,95.353 91.147,95.229 91.761,95.229 91.818,95.286 91.818,96.338 91.708,96.447 v1(91.402,96.447)
  Bottom Layer w0.2: v1(91.402,96.447) 91.776,96.447 91.785,96.438 91.785,94.833 91.913,94.705 92.65,94.705 93.863,93.493 95.005,93.493 95.255,93.243 95.255,86.922 94.95,86.617 v1(94.95,86.01)
AVDD: L2.2 U1.A4 U1.F2 | length 16.1
  Top Layer w0.2: v1(90.773,97.816) 91,97.589 U1.A4
  Inner2 w0.2: 89.721,95.724 v1(90.2,95.245)
  Inner2 w0.5: v1(84.179,87.035) 85.11,87.966 85.11,92.845 87.995,95.73 88.38,95.73 88.39,95.74 ; 88.42,95.724 89.721,95.724 89.721,95.779 89.615,95.885 89.615,97.02 90.411,97.816 v1(90.773,97.816)
CE0: U1.A7 X1.1 | length 39.3
  Top Layer w0.2: v1(84.467,83.965) 86.435,83.965 v1(86.707,83.692) ; U1.A7 92.195,97.25 92.195,97.67 92.526,98.001 92.526,100.141 92.78,100.395 93.185,100.395 93.45,100.66 X1.1
  Bottom Layer w0.2: v1@84.467,83.942 84.455,83.955 82.202,83.955 79.034,87.122 79.034,94.273 87.042,102.281 92.538,102.281 93.064,101.754 93.106,101.754 93.327,101.533 93.327,101.491 v1(93.443,101.375)
CS: CN1.3 U1.F7 | length 2.8
  Inner3 w0.2: v1(91.2,92.883) 91.698,93.381 91.698,94.4 92.198,94.901 v1(92.198,95.245)
DE0: U1.B6 X1.5 | length 23.9
  Top Layer w0.2: v1(92.705,83.725) 92.705,84.555 93.658,85.507 v1(94.333,85.507)
  Inner3 w0.2: v1(91.455,101.4) 91.455,98.333 91.8,97.988 v1(91.8,96.845)
  Bottom Layer w0.2: v1(91.8,96.845) 91.815,96.86 91.815,97.268 91.926,97.379 93.286,97.379 96.24,94.425 96.24,86.652 95.04,85.452 94.388,85.452 v1(94.333,85.507)
DGND: C30.2 C37.2 C38.1 C40.2 C41.2 CN1.5 CN1.9 CN1.10 CN1.11 CN1.12 CN1.13 CN1.14 R8.2 R9.1 U1.E4 U1.E5 U1.E6 U3.5 U3.8 U3.11 Y1.2 Y1.4 | length 0.8
  Top Layer w0.2: U1.E4 v1(91.4,95.645) ; v1(91.4,95.645) U1.E6
  other v1: 90.222,77.722 98.38,87.143 99.87,87.5 96.74,87.94 92.003,89.622 100.318,89.795 91.603,90.172 92.808,90.417 89.582,90.447 100.318,91.223 92.688,91.673 89.605,91.965 99.298,92.651 86.182,92.715 94.663,92.818 90.402,92.828 97.373,92.983 99.09,93.755 97.338,94.093 95.8,94.24
DVDD: L3.2 U1.F3 U1.G2 | length 29.3
  Inner2 w0.2: v1(90.2,94.845) 90.6,94.845 v1(90.6,95.245) ; v1(92.203,77.717) 94.903,77.717 98.283,81.097 98.283,84.19 v1(101.287,87.194)
  Inner2 w0.5: 90.7,94.735 94.46,90.975 97.23,90.975 101.011,87.194 v1(101.287,87.194)
GPIO0: U1.F5
GPIO1: U1.D6
GPIO2: U1.E1 | length 17.2
  Top Layer w0.2: v1(86.692,80.709) 87.445,81.462 87.445,86.677 v1(86.777,87.345)
  Top Layer w0.255: v1@88.435,94.835 89.245,95.645 U1.E1
  Bottom Layer w0.2: v1@86.647,80.617 v1@86.74,80.617 ; v1(86.777,87.345) 86.792,87.36 86.792,93.183 v1(88.435,94.825)
GPIO3: U1.E2
GPIO4: U1.G7 | length 19.7
  Top Layer w0.2: v1(88.202,80.702) 88.402,80.902 88.402,86.562 89.135,87.295 93.47,87.295 v1(93.653,87.477) ; U1.G7 92.2,94.233 v1(92.223,94.21)
  Bottom Layer w0.2: v1(92.223,94.21) 93.633,92.801 93.633,87.41 93.653,87.43 v1(93.653,87.477)
GPIO5: U1.F6
GPIO6: U1.F4
GPIO7: U1.G4 | length 15.1
  Top Layer w0.2: v1(89.697,80.697) 89.697,84.75 90.297,85.35 v1(90.455,85.35)
  Top Layer w0.255: v1(90.527,93.67) 91,94.143 U1.G4
  Bottom Layer w0.2: v1(90.455,85.35) 90.255,85.55 90.255,91.953 90.025,92.182 90.025,93.168 v1(90.527,93.67)
MISO: CN1.4 U1.E8 | length 6.1
  Top Layer w0.2: U1.E8 92.605,95.64 92.865,95.64 93.135,95.37 v1@93.135,94.905
  Inner3 w0.2: v1(90.792,92.169) 91.196,91.765 91.88,91.765 93.135,93.02 v1(93.135,94.94)
MOSI: CN1.8 U1.E7 | length 10.3
  Inner3 w0.2: v1(91.2,89.568) 91.812,88.956 93.087,88.956 93.699,89.568 ; v1(92.2,95.647) 93.332,95.647 93.699,95.28 93.699,89.593
RC0_0: C33.1 U1.C8 | length 6
  Top Layer w0.2: U1.C8 93.181,96.445 93.444,96.708 94.467,96.708 95.037,97.278 C33.1
  Top Layer w0.255: C33.1 97.136,97.422 97.855,96.703
RC0_1: C33.2 U1.B8 | length 10.5
  Top Layer w0.2: U1.B8 93.07,96.845 93.647,97.422 C33.2
  Top Layer w0.255: C33.2 94.123,97.496 94.123,97.53 94.678,98.085 100.455,98.085 101.816,96.725
RC0_2: U1.C6
RE0: U1.A8 X1.3 | length 28.2
  Top Layer w0.2: X1.3 92.424,101.403 92.424,101.961 92.883,102.42 93.841,102.42 94.123,102.138 94.123,100.835 93.801,100.514 93.801,98.289 92.757,97.245 U1.A8
  Bottom Layer w0.2: 89.665,83.572 89.665,84.947 87.56,87.052 87.56,92.81 89.07,94.32 89.07,96.646 90.617,98.193 93.695,98.193 v1(93.803,98.3)
RESET: CN1.6 U1.F1 | length 10.4
  Top Layer w0.2: U1.F1 89.533,95.245 87.896,93.608 87.13,93.608 86.865,93.343 86.865,90.537 87.63,89.772 90.287,89.772 CN1.6
SCLK: CN1.1 U1.F8 | length 2.9
  Inner3 w0.2: v1@92.01,92.545 92.6,93.135 v1(92.6,95.245)
  other v1: 92,92.54
SE0: U1.A6 X1.7 | length 29.2
  Top Layer w0.2: X1.7 90.452,101.375 90.452,100.81 90.82,100.443 91.035,100.443 91.251,100.227 91.251,98.527 91.8,97.978 U1.A6
  Bottom Layer w0.2: v1(90.44,101.748) 90.44,100.808 90.892,100.355 93.87,100.355 94.493,99.733 96.148,99.733 98.003,97.877 98.003,87.705 95.638,85.34 95.638,84.185
X0: C40.1 U1.G6 Y1.3 | length 7.3
  Top Layer w0.2: U1.G6 91.8,94.063 92.11,93.753 94.193,93.753 Y1.3
  Top Layer w0.255: Y1.3 94.617,94.283 94.617,94.659 94.953,94.995 97.211,94.995 C40.1
X1: C41.1 U1.G5 Y1.1 | length 9.1
  Top Layer w0.102: Y1.1@95.473,92.41 95.77,92.707 Y1.1
  Top Layer w0.2: U1.G5 91.395,93.64 91.703,93.333 93.023,93.333 93.488,92.868 93.488,92.25 93.67,92.068 95.229,92.068 95.473,92.311 Y1.1@95.473,92.41
  Top Layer w0.255: Y1.1@95.473,92.41 95.748,92.135 C41.1
pads on no net: U1.A1 U1.A2 U1.B2 U1.C2 U1.C3 U1.D3 U1.D4 U1.G1 U1.G8 U2.4 U3.4 X1.11 X1.12

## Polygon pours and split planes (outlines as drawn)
AGND on Inner1 (solid): 105.903,91.187 ccw(c91.127,91.187) 76.351,91.187 ccw(c91.127,91.187)
DGND on Inner4 (solid): 106.15,91.187 ccw(c91.234,91.187) 76.318,91.187 ccw(c91.234,91.187)

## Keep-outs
Board Outline Layer:
  circle w0.025: c100.2,100.2 r1
  region: 101.2,100.2 cw(c100.2,100.2) 99.2,100.2 cw(c100.2,100.2)
  circle w0.025: c100.2,82.2 r1
  region: 101.2,82.2 cw(c100.2,82.2) 99.2,82.2 cw(c100.2,82.2)
  circle w0.025: c82.2,82.2 r1
  region: 83.2,82.2 cw(c82.2,82.2) 81.2,82.2 cw(c82.2,82.2)
  circle w0.025: c82.2,100.2 r1
  region: 83.2,100.2 cw(c82.2,100.2) 81.2,100.2 cw(c82.2,100.2)
  lines w0.3: 86.057,105.296 96.34,105.293 ; 86.07,105.295 ccw(c91.2,91.2) 96.33,105.295 86.07,105.295

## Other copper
Top Layer:
  region net RC0_0: 96.8,97.6 98.8,97.6 98.8,95.6 96.8,95.6
  region net RC0_1: 100.8,97.6 102.8,97.6 102.8,95.6 100.8,95.6
  region net RC0_0: 94.947,97.046 94.681,97.063 ccw(c94.257,97.381) 94.787,97.381 95.265,97.152 ccw(c95.265,96.622)
  region net RC0_1: 93.647,97.322 93.647,97.522 ccw(c93.647,97.897) 93.947,97.672 93.947,97.172 ccw(c93.647,96.947)
  region net $1N4271: 92.728,96.145 92.728,95.945 92.65,95.942 92.6,95.938 92.6,96.152 92.65,96.148
  region net $1N8893: 100.195,93.342 100.45,93.342 ccw(c110.802,92.96) 100.443,92.96 100.193,92.96 ccw(c64.949,93.342)
  region net CE0: 92.095,97.368 92.295,97.378 92.3,97.314 92.307,97.25 92.093,97.24
  region net CE0: 93.55,100.66 93.35,100.66 ccw(c92.856,100.66) 93.3,100.877 93.6,100.877 ccw(c94.047,100.66)
  region net RE0: 92.324,101.961 92.524,101.961 ccw(c92.608,101.961) 92.6,101.877 92.3,101.877 ccw(c92.165,101.961)
  region net SE0: 90.552,100.81 90.352,100.81 ccw(c90.284,100.81) 90.3,100.877 90.6,100.877 ccw(c90.623,100.81)
  region net AVDD: 90.9,97.373 91.1,97.373 91.104,97.295 91.107,97.245 90.893,97.245 90.897,97.295
  region net AVDD: 90.95,97.781 90.809,97.639 90.769,97.673 90.734,97.697 90.704,97.714 90.685,97.728 90.862,97.904 90.876,97.885 90.893,97.856 90.916,97.82
  region net AIN2: 90.5,97.373 90.7,97.373 90.703,97.295 90.707,97.245 90.493,97.245 90.497,97.295
  region net SE0: 91.7,97.373 91.9,97.373 91.903,97.295 91.907,97.245 91.693,97.245 91.697,97.295
  region net $1N2152: 91.3,97.373 91.5,97.373 91.503,97.295 91.507,97.245 91.293,97.245 91.297,97.295
  region net $1N2152: 91.006,98.363 90.595,98.492 ccw(c90.215,98.112) 90.318,98.639 90.858,98.639 ccw(c91.391,98.747)
  region net AIN1: 89.238,98.12 89.38,98.262 89.419,98.228 89.455,98.205 89.484,98.187 89.503,98.173 89.327,97.997 89.313,98.016 89.296,98.045 89.272,98.081
  region net AIN1: 87.799,99.842 87.66,99.699 87.625,99.728 87.598,99.743 87.57,99.757 87.535,99.786 87.71,99.965 87.739,99.931 87.755,99.904 87.77,99.877
  region net RC0_0: 95.67,97.55 95.67,97.295 ccw(c95.67,96.71) 95.287,97.152 95.287,97.692 ccw(c95.67,98.134)
  region net RC0_1: 94.296,97.884 94.582,97.81 ccw(c95.123,97.404) 94.447,97.404 93.947,97.692 ccw(c93.791,98.389)
  region net RESET: 89.672,95.145 89.672,95.345 89.75,95.348 89.8,95.352 89.8,95.138 89.75,95.142
  region net $1N2188: 87.965,95.224 88.02,94.996 ccw(c88.444,94.678) 87.914,94.678 87.647,95.118 ccw(c87.647,95.648)
  region net $1N2188: 89.672,95.945 89.672,96.145 89.75,96.148 89.8,96.152 89.8,95.938 89.75,95.942
  region net GPIO2: 88.487,95.067 88.587,94.807 88.528,94.742 88.496,94.934 88.502,94.935 88.503,94.946 88.493,94.988 88.483,95.036 88.482,95.055
  region net X1: 91.499,94.717 91.299,94.717 91.296,94.796 91.293,94.846 91.507,94.845 91.503,94.795
  region net X0: 91.9,94.717 91.7,94.717 91.697,94.796 91.693,94.845 91.907,94.845 91.903,94.796
  region net GPIO4: 92.3,94.717 92.1,94.717 92.097,94.796 92.093,94.845 92.307,94.845 92.303,94.796
  region net GPIO4: 92.1,94.375 92.3,94.392 92.296,94.365 92.291,94.343 92.291,94.324 92.305,94.305 92.125,94.287 92.129,94.296 92.128,94.307 92.119,94.329 92.106,94.352
  region net RE0: 93.777,98.124 93.626,98.255 93.655,98.29 93.669,98.318 93.683,98.347 93.71,98.384 93.896,98.217 93.863,98.186 93.837,98.169 93.811,98.153
  region net RE0: 93.701,98.449 93.901,98.452 93.905,98.407 93.914,98.377 93.923,98.347 93.928,98.302 93.678,98.299 93.681,98.344 93.689,98.374 93.697,98.404
  region net CE0: 93.55,101.233 93.35,101.218 93.346,101.263 93.336,101.293 93.325,101.323 93.318,101.368 93.567,101.383 93.567,101.338 93.56,101.308 93.553,101.278
  region net CE0: 84.617,84.065 84.617,83.865 84.566,83.861 84.524,83.852 84.491,83.844 84.467,83.84 84.467,84.09 84.491,84.086 84.524,84.077 84.566,84.069
  region net CE0: 86.531,83.727 86.672,83.869 86.711,83.835 86.747,83.812 86.776,83.794 86.796,83.781 86.619,83.604 86.605,83.623 86.588,83.652 86.564,83.688
  region net GPIO2: 86.954,87.309 86.813,87.168 86.773,87.202 86.738,87.225 86.708,87.242 86.689,87.256 86.866,87.433 86.88,87.414 86.897,87.384 86.92,87.349
  region net GPIO2: 86.728,80.886 86.869,80.745 86.835,80.706 86.812,80.67 86.795,80.641 86.781,80.621 86.604,80.798 86.623,80.812 86.653,80.829 86.688,80.853
  region net AIN2: 91.85,101.56 92.05,101.591 92.055,101.545 92.066,101.516 92.079,101.486 92.089,101.441 91.841,101.41 91.839,101.449 91.843,101.485 91.847,101.521
  region net DE0: 92.605,83.875 92.805,83.875 92.809,83.823 92.818,83.781 92.826,83.748 92.83,83.725 92.58,83.725 92.584,83.748 92.593,83.781 92.601,83.823
  region net AIN6: 95.05,85.86 94.85,85.86 94.846,85.911 94.838,85.953 94.829,85.986 94.825,86.01 95.075,86.01 95.071,85.986 95.063,85.953 95.054,85.911
  region net AIN6: 94.233,80.874 94.374,80.732 94.341,80.693 94.317,80.657 94.3,80.628 94.286,80.609 94.109,80.785 94.129,80.799 94.158,80.816 94.194,80.84
  region net DE0: 94.183,85.407 94.183,85.607 94.234,85.611 94.276,85.62 94.309,85.628 94.333,85.632 94.333,85.382 94.309,85.386 94.276,85.395 94.234,85.403
  region net AIN2: 91.233,83.881 91.374,83.74 91.341,83.701 91.317,83.665 91.3,83.636 91.286,83.616 91.109,83.793 91.129,83.807 91.158,83.824 91.194,83.848
  region net AIN2: 96.824,85.085 96.965,85.226 97.004,85.193 97.04,85.169 97.069,85.152 97.089,85.138 96.912,84.961 96.898,84.981 96.881,85.01 96.857,85.046
  region net GPIO7: 89.597,80.847 89.797,80.847 89.801,80.795 89.81,80.753 89.819,80.721 89.822,80.697 89.572,80.697 89.576,80.721 89.585,80.753 89.594,80.795
  region net AIN0: 89.842,86.927 89.842,86.727 89.791,86.723 89.749,86.715 89.716,86.706 89.692,86.702 89.692,86.952 89.716,86.948 89.749,86.94 89.791,86.931
  region net AIN0: 92.531,80.732 92.672,80.874 92.711,80.84 92.747,80.816 92.777,80.799 92.796,80.785 92.619,80.609 92.605,80.628 92.588,80.657 92.564,80.693
  region net GPIO4: 88.238,80.879 88.379,80.737 88.345,80.698 88.322,80.662 88.305,80.633 88.291,80.614 88.114,80.79 88.133,80.804 88.163,80.821 88.199,80.845
  region net GPIO4: 93.617,87.301 93.476,87.442 93.51,87.481 93.533,87.517 93.55,87.546 93.564,87.566 93.741,87.389 93.722,87.375 93.692,87.358 93.656,87.334
  region net X0: 96.645,94.867 96.645,95.122 ccw(c96.645,97.213) 97.028,95.158 97.028,94.676 ccw(c96.645,94.389)
  region net X0: 94.635,94.857 95.043,94.905 ccw(c95.145,94.803) 95.07,94.68 94.27,94.68 ccw(c94.198,95.294)
  region net X0: 94.263,93.682 94.164,93.865 ccw(c93.74,94.184) 94.27,94.184 94.574,93.78 ccw(c94.574,93.241)
  region net X1: 96.723,92.007 96.723,92.262 ccw(c96.723,92.921) 97.105,92.385 97.105,91.885 ccw(c96.723,91.349)
Inner2:
  region net DVDD: 92.353,77.817 92.353,77.617 92.301,77.613 92.259,77.604 92.226,77.596 92.203,77.592 92.203,77.842 92.226,77.838 92.259,77.829 92.301,77.821
  region net +3.3VD: 97.295,88.469 97.18,88.301 ccw(c96.069,87.189) 96.769,88.597 96.989,88.869 ccw(c98.65,89.823)
  region net +3.3VD: 95.751,80.876 95.892,80.735 95.858,80.696 95.835,80.66 95.818,80.631 95.804,80.611 95.627,80.788 95.646,80.802 95.676,80.819 95.711,80.843
  region net DVDD: 101.252,87.017 101.111,87.159 101.144,87.198 101.168,87.234 101.185,87.263 101.199,87.283 101.376,87.106 101.356,87.092 101.327,87.075 101.291,87.051
Inner3:
  region net CS: 92.298,95.095 92.098,95.095 92.094,95.146 92.085,95.189 92.077,95.221 92.073,95.245 92.323,95.245 92.319,95.221 92.31,95.189 92.302,95.146
  region net AIN3: 91.05,101.227 90.85,101.227 90.846,101.279 90.837,101.321 90.829,101.353 90.825,101.377 91.075,101.377 91.071,101.353 91.062,101.321 91.054,101.279
  region net AIN1: 89.587,97.969 89.392,97.882 89.382,97.895 89.378,97.907 89.379,97.932 89.378,97.955 89.372,97.964 89.359,97.973 89.53,98.035 89.526,98.022 89.527,98.013 89.541,97.999 89.563,97.987
  region net AIN1: 87.522,100.025 87.722,100.025 87.726,99.974 87.735,99.932 87.743,99.899 87.747,99.875 87.497,99.875 87.501,99.899 87.51,99.932 87.518,99.974
  region net AIN0: 90.05,95.945 90.05,96.145 90.102,96.149 90.144,96.158 90.176,96.166 90.2,96.17 90.2,95.92 90.176,95.924 90.144,95.933 90.102,95.941
  region net $1N2048: 95.65,98.948 95.65,99.148 95.702,99.152 95.744,99.16 95.777,99.169 95.8,99.173 95.8,98.923 95.777,98.927 95.744,98.935 95.702,98.944
  region net CS: 91.235,93.06 91.377,92.918 91.343,92.879 91.319,92.843 91.302,92.814 91.288,92.795 91.112,92.971 91.131,92.985 91.16,93.002 91.196,93.026
Bottom Layer:
  region net AIN1: 87.7,84.7 88.7,84.7 88.7,82.7 87.7,82.7
  region net RE0: 89.2,84.7 90.2,84.7 90.2,82.7 89.2,82.7
  region net AIN2: 90.7,84.7 91.7,84.7 91.7,82.7 90.7,82.7
  region net DE0: 92.2,84.7 93.2,84.7 93.2,82.7 92.2,82.7
  region net AIN3: 93.7,84.7 94.7,84.7 94.7,82.7 93.7,82.7
  region net SE0: 95.2,84.7 96.2,84.7 96.2,82.7 95.2,82.7
  region net AIN4: 90.7,81.7 91.7,81.7 91.7,79.7 90.7,79.7
  region net CE0: 86.2,84.7 87.2,84.7 87.2,82.7 86.2,82.7
  region net AIN0: 92.2,81.7 93.2,81.7 93.2,79.7 92.2,79.7
  region net AIN6: 93.7,81.7 94.7,81.7 94.7,79.7 93.7,79.7
  region net GPIO2: 86.2,81.7 87.2,81.7 87.2,79.7 86.2,79.7
  region net GPIO4: 87.7,81.7 88.7,81.7 88.7,79.7 87.7,79.7
  region net GPIO7: 89.2,81.7 90.2,81.7 90.2,79.7 89.2,79.7
  region net DVDD: 91.7,78.7 92.7,78.7 92.7,76.7 91.7,76.7
  region net DGND: 89.7,78.7 90.7,78.7 90.7,76.7 89.7,76.7
  region net +3.3VD: 95.2,81.7 96.2,81.7 96.2,79.7 95.2,79.7
  region net GPIO7: 90.492,93.493 90.351,93.635 90.384,93.674 90.408,93.71 90.425,93.739 90.439,93.759 90.616,93.582 90.596,93.568 90.567,93.551 90.531,93.527
  region net GPIO4: 92.4,94.175 92.258,94.033 92.219,94.067 92.183,94.091 92.154,94.108 92.135,94.122 92.311,94.299 92.325,94.279 92.342,94.25 92.366,94.214
  region net AIN1: 87.722,99.725 87.522,99.725 87.518,99.777 87.51,99.819 87.501,99.852 87.497,99.875 87.747,99.875 87.743,99.852 87.735,99.819 87.726,99.777
  region net SE0: 90.54,101.598 90.34,101.598 90.336,101.65 90.327,101.692 90.319,101.724 90.315,101.748 90.565,101.748 90.561,101.724 90.552,101.692 90.544,101.65
  region net AIN0: 90.3,95.895 90.1,95.895 90.096,95.947 90.088,95.989 90.079,96.021 90.075,96.045 90.325,96.045 90.321,96.021 90.313,95.989 90.304,95.947
  region net GPIO2: 88.4,94.648 88.258,94.79 88.292,94.829 88.315,94.865 88.333,94.894 88.346,94.914 88.523,94.737 88.504,94.723 88.475,94.706 88.439,94.682
  region net GPIO2: 86.692,87.51 86.892,87.48 86.895,87.44 86.899,87.405 86.903,87.369 86.901,87.33 86.653,87.36 86.663,87.405 86.676,87.435 86.687,87.464
  region net AIN6: 94.85,86.16 95.05,86.16 95.054,86.108 95.063,86.066 95.071,86.033 95.075,86.01 94.825,86.01 94.829,86.033 94.838,86.066 94.846,86.108
  region net AIN0: 89.55,86.72 89.535,86.92 89.58,86.924 89.61,86.934 89.64,86.945 89.685,86.952 89.7,86.703 89.655,86.703 89.625,86.709 89.595,86.716
  region net DE0: 94.534,85.552 94.465,85.352 94.45,85.355 94.438,85.361 94.42,85.378 94.403,85.392 94.392,85.394 94.378,85.391 94.447,85.558 94.454,85.547 94.462,85.541 94.481,85.541 94.505,85.548
  region net AIN2: 97.15,85.15 97.15,84.95 97.099,84.946 97.057,84.937 97.024,84.929 97,84.925 97,85.175 97.024,85.171 97.057,85.162 97.099,85.154
  region net AIN4: 90.055,101.232 89.855,101.222 89.851,101.267 89.841,101.297 89.831,101.327 89.825,101.372 90.075,101.382 90.073,101.338 90.066,101.307 90.058,101.277
  region net CE0: 84.327,83.855 84.307,84.055 84.352,84.059 84.382,84.07 84.412,84.081 84.457,84.089 84.477,83.84 84.433,83.84 84.402,83.845 84.372,83.852
  region net AIN2: 92.05,101.26 91.85,101.29 91.848,101.33 91.843,101.366 91.84,101.401 91.841,101.441 92.089,101.41 92.079,101.365 92.066,101.336 92.055,101.306
  region net GPIO7: 90.278,85.385 90.42,85.526 90.459,85.493 90.495,85.469 90.524,85.452 90.543,85.438 90.367,85.261 90.353,85.281 90.336,85.31 90.312,85.346

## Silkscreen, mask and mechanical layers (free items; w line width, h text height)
Top Silkscreen Layer:
  drawing of 35 lines, arcs and shapes, not listed
  text "RC0" at 98.375,97.485 h1.5
Bottom Silkscreen Layer:
  drawing of 192 lines, arcs and shapes, not listed
  text "SE0" at 95.158,90.867 h1.54 r270
  text "DE0" at 92.15,90.822 h1.54 r270
  text "AIN1" at 87.57,90.797 h1.54 r270
  text "RE0" at 89.09,90.799 h1.54 r270
  text "CE0" at 86.005,90.77 h1.54 r270
  text "AIN3" at 93.7,90.78 h1.54 r270
  text "AIN2" at 90.64,90.722 h1.54 r270
  text "AIN4" at 89.872,85.427 h1.54 r270
  text "GPIO2" at 84.937,85.367 h1.54 r270
  text "GPIO7" at 88.232,85.362 h1.54 r270
  text "AIN0" at 91.308,85.377 h1.54 r270
  text "AIN6" at 92.708,85.365 h1.54 r270
  text "GPIO4" at 86.627,85.355 h1.54 r270
  text "+3.3VD" at 94.13,85.225 h1.54 r270
  text "DVDD" at 92.958,79.107 h1.54 r180
  text "DGND" at 85.52,79.044 h1.54 r180
Top Solder Mask Layer:
  region: 100.795,97.593 102.795,97.593 102.795,95.593 100.795,95.593
  region: 96.795,97.593 98.795,97.593 98.795,95.593 96.795,95.593
Bottom Solder Mask Layer:
  region: 86.2,84.699 87.2,84.699 87.2,82.699 86.2,82.699
  region: 87.7,84.699 88.7,84.699 88.7,82.699 87.7,82.699
  region: 89.2,84.699 90.2,84.699 90.2,82.699 89.2,82.699
  region: 90.7,84.699 91.7,84.699 91.7,82.699 90.7,82.699
  region: 92.2,84.699 93.2,84.699 93.2,82.699 92.2,82.699
  region: 93.7,84.699 94.7,84.699 94.7,82.699 93.7,82.699
  region: 95.2,84.699 96.2,84.699 96.2,82.699 95.2,82.699
  region: 86.2,81.699 87.2,81.699 87.2,79.699 86.2,79.699
  region: 87.7,81.699 88.7,81.699 88.7,79.699 87.7,79.699
  region: 89.2,81.699 90.2,81.699 90.2,79.699 89.2,79.699
  region: 90.7,81.699 91.7,81.699 91.7,79.699 90.7,79.699
  region: 92.2,81.699 93.2,81.699 93.2,79.699 92.2,79.699
  region: 93.7,81.699 94.7,81.699 94.7,79.699 93.7,79.699
  region: 91.7,78.699 92.7,78.699 92.7,76.699 91.7,76.699
  region: 89.7,78.699 90.7,78.699 90.7,76.699 89.7,76.699
  region: 95.2,81.699 96.2,81.699 96.2,79.699 95.2,79.699
Mechanical Layer:
  circle w0.025: c100.2,100.2 r1
  circle w0.025: c100.2,82.2 r1
  circle w0.025: c82.2,82.2 r1
  circle w0.025: c82.2,100.2 r1
Mech6:
  lines w0.254: 88.587,89.405 93.787,89.405 93.787,93.055 88.587,93.055 88.587,89.405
